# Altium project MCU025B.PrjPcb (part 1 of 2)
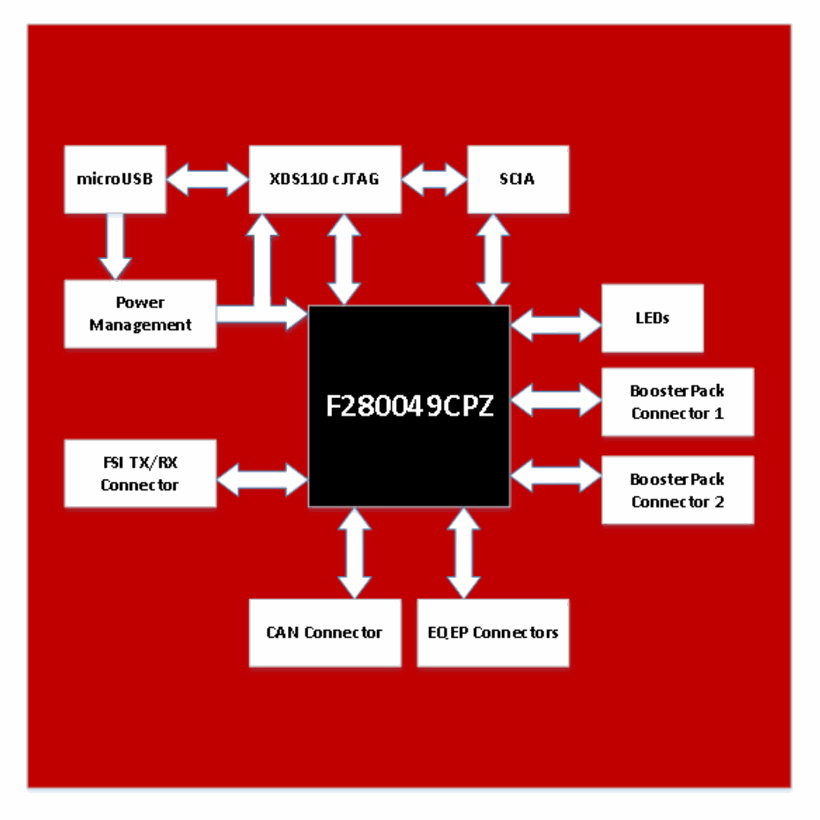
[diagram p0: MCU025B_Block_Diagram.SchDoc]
CopyrightYear: 2019; PCB_Layout: a0232540; PCB_Rev: B; PRJ_Customer: Public Release; PRJ_Engineer: a0232540; PRJ_Number: MCU025; PRJ_Title: LAUNCHXL-F280049C; SCH_Rev: B; TechSupport: http://www.ti.com/support; TID: N/A
8 sheets, 239 parts. Net scope: global (net labels, ports and power ports of the same name join across sheets).
Board file: MCU025B.PcbDoc
Sheets:
  MCU025B_Block_Diagram.SchDoc
  MCU025B_Connectors.SchDoc
  MCU025B_AltRouting_Misc.SchDoc
  MCU025B_F280049C_Device.SchDoc
  MCU025B_XDS110_Target_Interface.SchDoc
  MCU025B_XDS110_USB_Power.SchDoc
  MCU025B_XDS110_MCU.SchDoc
  MCU025B_Hardware.SchDoc

## Sheet MCU025B_Block_Diagram.SchDoc
size 431 x 279 mm; Date: Not shown in title block; ApprovedBy: Not shown in title block; CheckedBy: Not shown in title block; Author: Not shown in title block; CompanyName: Not shown in title block; Engineer: Not shown in title block; Organization: Not shown in title block; Address1: Not shown in title block; Address2: Not shown in title block; Address3: Not shown in title block; Address4: Not shown in title block; DocumentNumber: 1; Revision: Use project parameter SCH_Rev; SheetNumber: 1; SheetTotal: 8; PageSetup: Record=PageOptions¦CenterHorizontal=True¦CenterVertical=True¦PrintScale=1.00¦XCorrection=1.00¦YCorrection=1.00¦PrintKind=0¦BorderSize=5000000¦LeftOffset=0¦BottomOffset=0¦Orientation=2¦PaperLength=1000¦PaperWidth=1000¦Scale=100¦PaperSource=15¦PrintQuality=600¦MediaType=1¦DitherType=10¦PaperKind=Letter¦PrintScaleMode=1

## Sheet MCU025B_Connectors.SchDoc
size 431 x 279 mm; Date: Not shown in title block; ApprovedBy: Not shown in title block; CheckedBy: Not shown in title block; Author: Not shown in title block; CompanyName: Not shown in title block; Engineer: Not shown in title block; Organization: Not shown in title block; Address1: Not shown in title block; Address2: Not shown in title block; Address3: Not shown in title block; Address4: Not shown in title block; DocumentNumber: 2; Revision: Use project parameter SCH_Rev; SheetNumber: 2; SheetTotal: 8; PageSetup: Record=PageOptions¦CenterHorizontal=True¦CenterVertical=True¦PrintScale=1.00¦XCorrection=1.00¦YCorrection=1.00¦PrintKind=0¦BorderSize=5000000¦LeftOffset=0¦BottomOffset=0¦Orientation=2¦PaperLength=1000¦PaperWidth=1000¦Scale=100¦PaperSource=15¦PrintQuality=600¦MediaType=1¦DitherType=10¦PaperKind=Letter¦PrintScaleMode=1
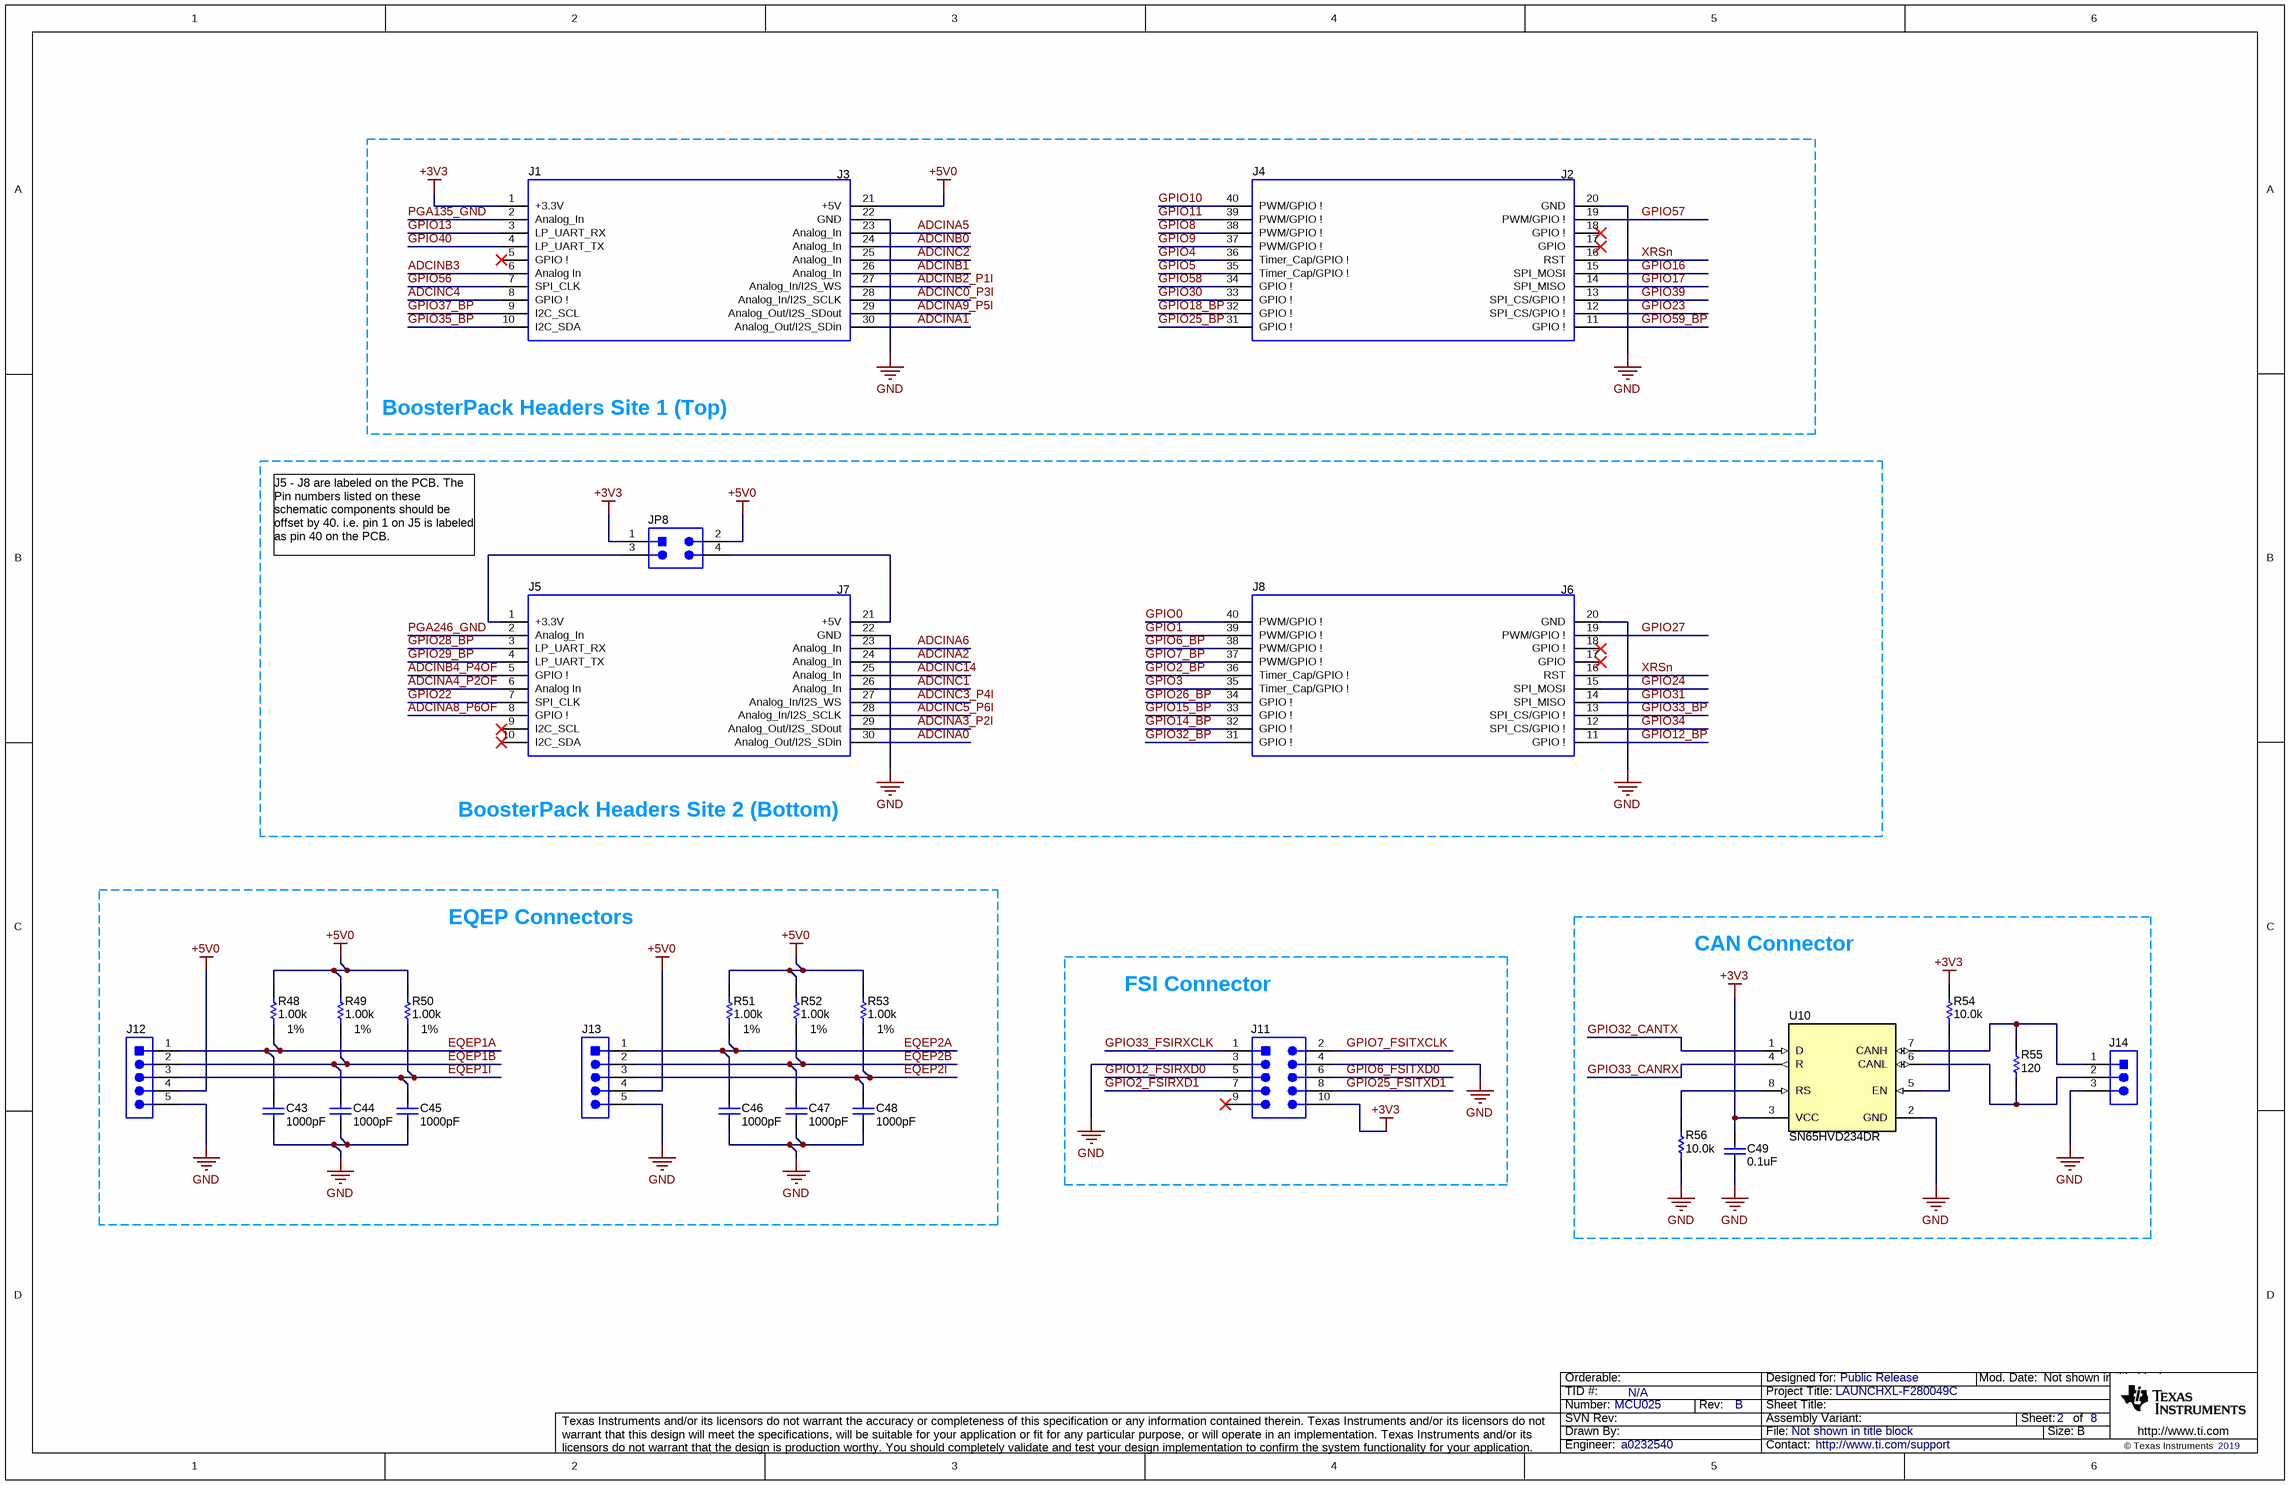
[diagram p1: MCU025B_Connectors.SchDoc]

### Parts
C43  ValueDisplayed: 1000pF  [0402]  (hidden comment: GRM155R71H102KA01D)
C44  ValueDisplayed: 1000pF  [0402]  (hidden comment: GRM155R71H102KA01D)
C45  ValueDisplayed: 1000pF  [0402]  (hidden comment: GRM155R71H102KA01D)
C46  ValueDisplayed: 1000pF  [0402]  (hidden comment: GRM155R71H102KA01D)
C47  ValueDisplayed: 1000pF  [0402]  (hidden comment: GRM155R71H102KA01D)
C48  ValueDisplayed: 1000pF  [0402]  (hidden comment: GRM155R71H102KA01D)
C49  ValueDisplayed: 0.1uF  [0402]  (hidden comment: GRM155R71A104KA01D)
J1  SSQ-110-03-T-D  [BoosterPack_40pin_J1J3]  (value not drawn)
J4  SSQ-110-03-T-D  [BoosterPack_40pin_J2J4]  (value not drawn)
J5  SSQ-110-03-T-D  [BoosterPack_40pin_J1J3]  (value not drawn)
J8  SSQ-110-03-T-D  [BoosterPack_40pin_J2J4]  (value not drawn)
J11  TSW-105-07-G-D  [TSW-105-07-G-D]  (value not drawn)
J12  TSW-105-07-G-S  [TSW-105-07-X-S]  (value not drawn)
J13  TSW-105-07-G-S  [TSW-105-07-X-S]  (value not drawn)
J14  61300311121  [WURTH_61300311121]  (value not drawn)
JP8  TSW-102-07-G-D  [TSW-102-07-G-D]  (value not drawn)
R48  ValueDisplayed: 1.00k  Value1: 1%  [0402]  (hidden comment: CRCW04021K00FKED)
R49  ValueDisplayed: 1.00k  Value1: 1%  [0402]  (hidden comment: CRCW04021K00FKED)
R50  ValueDisplayed: 1.00k  Value1: 1%  [0402]  (hidden comment: CRCW04021K00FKED)
R51  ValueDisplayed: 1.00k  Value1: 1%  [0402]  (hidden comment: CRCW04021K00FKED)
R52  ValueDisplayed: 1.00k  Value1: 1%  [0402]  (hidden comment: CRCW04021K00FKED)
R53  ValueDisplayed: 1.00k  Value1: 1%  [0402]  (hidden comment: CRCW04021K00FKED)
R54  ValueDisplayed: 10.0k  [0402]  (hidden comment: CRCW040210K0FKED)
R55  ValueDisplayed: 120  [0603]  (hidden comment: RC0603FR-07120RL)
R56  ValueDisplayed: 10.0k  [0402]  (hidden comment: CRCW040210K0FKED)
U10  SN65HVD234DR  [D0008A_L]

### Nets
+3V3: C49.2 J1.1(+3.3V) J11.10 JP8.1 R54.2 U10.3(VCC)
+5V0: J1.21(+5V) J12.4 J13.4 JP8.2 R48.2 R49.2 R50.2 R51.2 R52.2 R53.2
GND: C43.2 C44.2 C45.2 C46.2 C47.2 C48.2 C49.1 J1.22(GND) J4.20(GND) J5.22(GND) J8.20(GND) J11.3 J11.4 J12.5 J13.5 J14.3 R56.1 U10.2(GND)
ADCINA0: J5.30(Analog_Out/I2S_SDin)
ADCINA1: J1.30(Analog_Out/I2S_SDin)
ADCINA2: J5.24(Analog_In)
ADCINA3_P2I: J5.29(Analog_Out/I2S_SDout)
ADCINA4_P2OF: J5.6(Analog_In)
ADCINA5: J1.23(Analog_In)
ADCINA6: J5.23(Analog_In)
ADCINA8_P6OF: J5.8(GPIO_!)
ADCINA9_P5I: J1.29(Analog_Out/I2S_SDout)
ADCINB0: J1.24(Analog_In)
ADCINB1: J1.26(Analog_In)
ADCINB2_P1I: J1.27(Analog_In/I2S_WS)
ADCINB3: J1.6(Analog_In)
ADCINB4_P4OF: J5.5(GPIO_!)
ADCINC0_P3I: J1.28(Analog_In/I2S_SCLK)
ADCINC1: J5.26(Analog_In)
ADCINC2: J1.25(Analog_In)
ADCINC3_P4I: J5.27(Analog_In/I2S_WS)
ADCINC4: J1.8(GPIO_!)
ADCINC5_P6I: J5.28(Analog_In/I2S_SCLK)
ADCINC14: J5.25(Analog_In)
EQEP1A: C43.1 J12.1 R48.1
EQEP1B: C44.1 J12.2 R49.1
EQEP1I: C45.1 J12.3 R50.1
EQEP2A: C46.1 J13.1 R51.1
EQEP2B: C47.1 J13.2 R52.1
EQEP2I: C48.1 J13.3 R53.1
GPIO0: J8.40(PWM/GPIO_!)
GPIO1: J8.39(PWM/GPIO_!)
GPIO2_BP: J8.36(Timer_Cap/GPIO_!)
GPIO2_FSIRXD1: J11.7
GPIO3: J8.35(Timer_Cap/GPIO_!)
GPIO4: J4.36(Timer_Cap/GPIO_!)
GPIO5: J4.35(Timer_Cap/GPIO_!)
GPIO6_BP: J8.38(PWM/GPIO_!)
GPIO6_FSITXD0: J11.6
GPIO7_BP: J8.37(PWM/GPIO_!)
GPIO7_FSITXCLK: J11.2
GPIO8: J4.38(PWM/GPIO_!)
GPIO9: J4.37(PWM/GPIO_!)
GPIO10: J4.40(PWM/GPIO_!)
GPIO11: J4.39(PWM/GPIO_!)
GPIO12_BP: J8.11(GPIO_!)
GPIO12_FSIRXD0: J11.5
GPIO13: J1.3(LP_UART_RX)
GPIO14_BP: J8.32(GPIO_!)
GPIO15_BP: J8.33(GPIO_!)
GPIO16: J4.15(SPI_MOSI)
GPIO17: J4.14(SPI_MISO)
GPIO18_BP: J4.32(GPIO_!)
GPIO22: J5.7(SPI_CLK)
GPIO23: J4.12(SPI_CS/GPIO_!)
GPIO24: J8.15(SPI_MOSI)
GPIO25_BP: J4.31(GPIO_!)
GPIO25_FSITXD1: J11.8
GPIO26_BP: J8.34(GPIO_!)
GPIO27: J8.19(PWM/GPIO_!)
GPIO28_BP: J5.3(LP_UART_RX)
GPIO29_BP: J5.4(LP_UART_TX)
GPIO30: J4.33(GPIO_!)
GPIO31: J8.14(SPI_MISO)
GPIO32_BP: J8.31(GPIO_!)
GPIO32_CANTX: U10.1(D)
GPIO33_BP: J8.13(SPI_CS/GPIO_!)
GPIO33_CANRX: U10.4(R)
GPIO33_FSIRXCLK: J11.1
GPIO34: J8.12(SPI_CS/GPIO_!)
GPIO35_BP: J1.10(I2C_SDA)
GPIO37_BP: J1.9(I2C_SCL)
GPIO39: J4.13(SPI_CS/GPIO_!)
GPIO40: J1.4(LP_UART_TX)
GPIO56: J1.7(SPI_CLK)
GPIO57: J4.19(PWM/GPIO_!)
GPIO58: J4.34(GPIO_!)
GPIO59_BP: J4.11(GPIO_!)
PGA135_GND: J1.2(Analog_In)
PGA246_GND: J5.2(Analog_In)
XRSn: J4.16(RST) J8.16(RST)
NetJ5_1: J5.1(+3.3V) JP8.3
NetJ5_21: J5.21(+5V) JP8.4
NetJ14_1: J14.1 R55.2 U10.7(CANH)
NetJ14_2: J14.2 R55.1 U10.6(CANL)
NetR54_1: R54.1 U10.5(EN)
NetR56_2: R56.2 U10.8(RS)

Not connected (* = marked no-connect by the designer): J1 5(GPIO_!)*; J4 17(GPIO)* 18(GPIO_!)*; J5 9(I2C_SCL)* 10(I2C_SDA)*; J8 17(GPIO)* 18(GPIO_!)*; J11 9*

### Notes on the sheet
- (near J1) J3
- (near J4) J2
- BoosterPack Headers Site 1 (Top)
- J5 - J8 are labeled on the PCB. The Pin numbers listed on these schematic components should be offset by 40. i.e. pin 1 on J5 is labeled as pin 40 on the PCB.
- (near J5) J7
- (near J8) J6
- BoosterPack Headers Site 2 (Bottom)
- EQEP Connectors
- CAN Connector
- FSI Connector

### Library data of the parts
C43-C48 = CMP-0006673-2: CAP, CERM, 1000 pF, 50 V, +/- 10%, X7R, 0402; Manufacturer: MuRata; Polarized: N; Value: 1000pF; U/M: EA; Cap_F: 1nF; Value1: Unknown; VDC_V: 50V; TaMin_C: -55°C; TaMax_C: 125°C; SizeArea_mm2: 0.5; SizeAreaWB_mm2: 3; SizeX_mm: 1; SizeZ_mm: 0.6; AEC Category: Q200
C49 = CMP-0006629-2: CAP, CERM, 0.1 uF, 10 V, +/- 10%, X7R, 0402; Manufacturer: MuRata; Polarized: N; Value: 0.1uF; U/M: EA; Cap_F: 100nF; Value1: Unknown; VDC_V: 10V; TaMin_C: -55°C; TaMax_C: 125°C; SizeArea_mm2: 0.5; SizeAreaWB_mm2: 3; SizeX_mm: 1; SizeZ_mm: 0.6; AEC Category: Q200
J1 J5 = CMP-0003837-2: Receptacle, 2.54mm, 10x2, Tin, TH; Manufacturer: Samtec; Alternate Manufacturer: Major League Electronics; Alternate PartNumber: CRD-081413-A-G; Note: Booster Pack 40 pin J1 and J3; Green_Lifecycle: Active; Green_REACh: Incomplete
J4 J8 = CMP-0078266-2: Receptacle, 2.54mm, 10x2, Tin, TH; Manufacturer: Samtec; Alternate Manufacturer: Major League Electronics; Alternate PartNumber: CRD-081413-A-G; Note: Booster Pack 40 pin J2 and J4; Green_Lifecycle: Active; Green_REACh: Incomplete
J11 = CMP-0075410-2: Header, 100mil, 5x2, Gold, TH; Manufacturer: Samtec; Pitch_mm: 2.54; Cert_VDE: N; Gender: Male; Cert_CSA: Y; Voltage_V: 550V; Green_REACh: Passed; Current_A: 6.3A; Green_Lifecycle: Active; Row_Count: 2
J12 J13 = CMP-0075411-1: Header, 100mil, 5x1, Gold, TH; Manufacturer: Samtec; Pitch_mm: 2.54; Cert_VDE: N; Gender: Male; Cert_CSA: Y; Voltage_V: 550V; Green_REACh: Passed; Current_A: 6.3A; CT: False; Green_Lifecycle: Active; Row_Count: 1; CNHeader: True
J14 = CMP-0054796-1: Header, 2.54 mm, 3x1, Gold, TH; Manufacturer: Wurth Elektronik; Green_Lifecycle: Active; Green_REACh: Passed; CNHeader: TRUE; CT: FALSE
JP8 = CMP-0075404-1: Header, 100mil, 2x2, Gold, TH; Manufacturer: Samtec; CNHeader: True; Shrouded: N; Gender: Male; Row_Count: 2; RowSpacing_mm: 2.54; CT: False; Cert_CSA: Y; Current_A: 6.3A; Green_Lifecycle: Active; Green_REACh: Passed; Voltage_V: 550V
R48-R53 = CMP-0026071-3: RES, 1.00 k, 1%, 0.063 W, AEC-Q200 Grade 0, 0402; Manufacturer: Vishay-Dale; Value: 1.00k; Res_ohm: 1k; Value_Code: 1k00; Power_W: 63mW; Value2: 0.063W; VDC_V: 50V; TempCo: 100 ppm/C; SizeArea_mm2: 0.5; SizeX_mm: 1; SizeZ_mm: 0.6; EIA_Code: E96; AEC Category: Q200; AEC Qualified: Y; AEC Grade: 0
R54 R56 = CMP-0025958-3: RES, 10.0 k, 1%, 0.063 W, AEC-Q200 Grade 0, 0402; Manufacturer: Vishay-Dale; Value: 10.0k; Res_ohm: 10k; Value_Code: 10k0; Power_W: 63mW; Value2: 0.063W; VDC_V: 50V; TempCo: 100 ppm/C; SizeArea_mm2: 0.5; SizeX_mm: 1; SizeZ_mm: 0.6; EIA_Code: E96; AEC Category: Q200; AEC Qualified: Y; AEC Grade: 0
R55 = CMP-0022769-3: RES, 120, 1%, 0.1 W, 0603; Manufacturer: Yageo America; Value: 120; Value_Code: 120R; Power_W: 100mW; Value2: 0.1W; VDC_V: 150V; TempCo: 200 ppm/C; SizeArea_mm2: 1.28; SizeX_mm: 1.6; SizeY_mm: 0.8; SizeZ_mm: 1; U/M: EA; AEC Category: Q200
U10 = CMP-0033355-1: 3.3V CAN Transceiver with Sleep Mode, 6 mA, -40 to 125 degC, 8-pin SOIC (D), Green (RoHS & no Sb/Br); Manufacturer: Texas Instruments; Drivers Per Package: 1; Bus Fault Voltage(V): +/-30; Transient Pulse Protection(V): -100 to 100; ICC(Max)(mA): 6; Supply Voltage(s)(V): 3.3; Rating: Catalog

## Sheet MCU025B_AltRouting_Misc.SchDoc
size 431 x 279 mm; Date: Not shown in title block; ApprovedBy: Not shown in title block; CheckedBy: Not shown in title block; Author: Not shown in title block; CompanyName: Not shown in title block; Engineer: Not shown in title block; Organization: Not shown in title block; Address1: Not shown in title block; Address2: Not shown in title block; Address3: Not shown in title block; Address4: Not shown in title block; DocumentNumber: 3; Revision: Use project parameter SCH_Rev; SheetNumber: 3; SheetTotal: 8; PageSetup: Record=PageOptions¦CenterHorizontal=True¦CenterVertical=True¦PrintScale=1.00¦XCorrection=1.00¦YCorrection=1.00¦PrintKind=0¦BorderSize=5000000¦LeftOffset=0¦BottomOffset=0¦Orientation=2¦PaperLength=1000¦PaperWidth=1000¦Scale=100¦PaperSource=15¦PrintQuality=600¦MediaType=1¦DitherType=10¦PaperKind=Letter¦PrintScaleMode=1
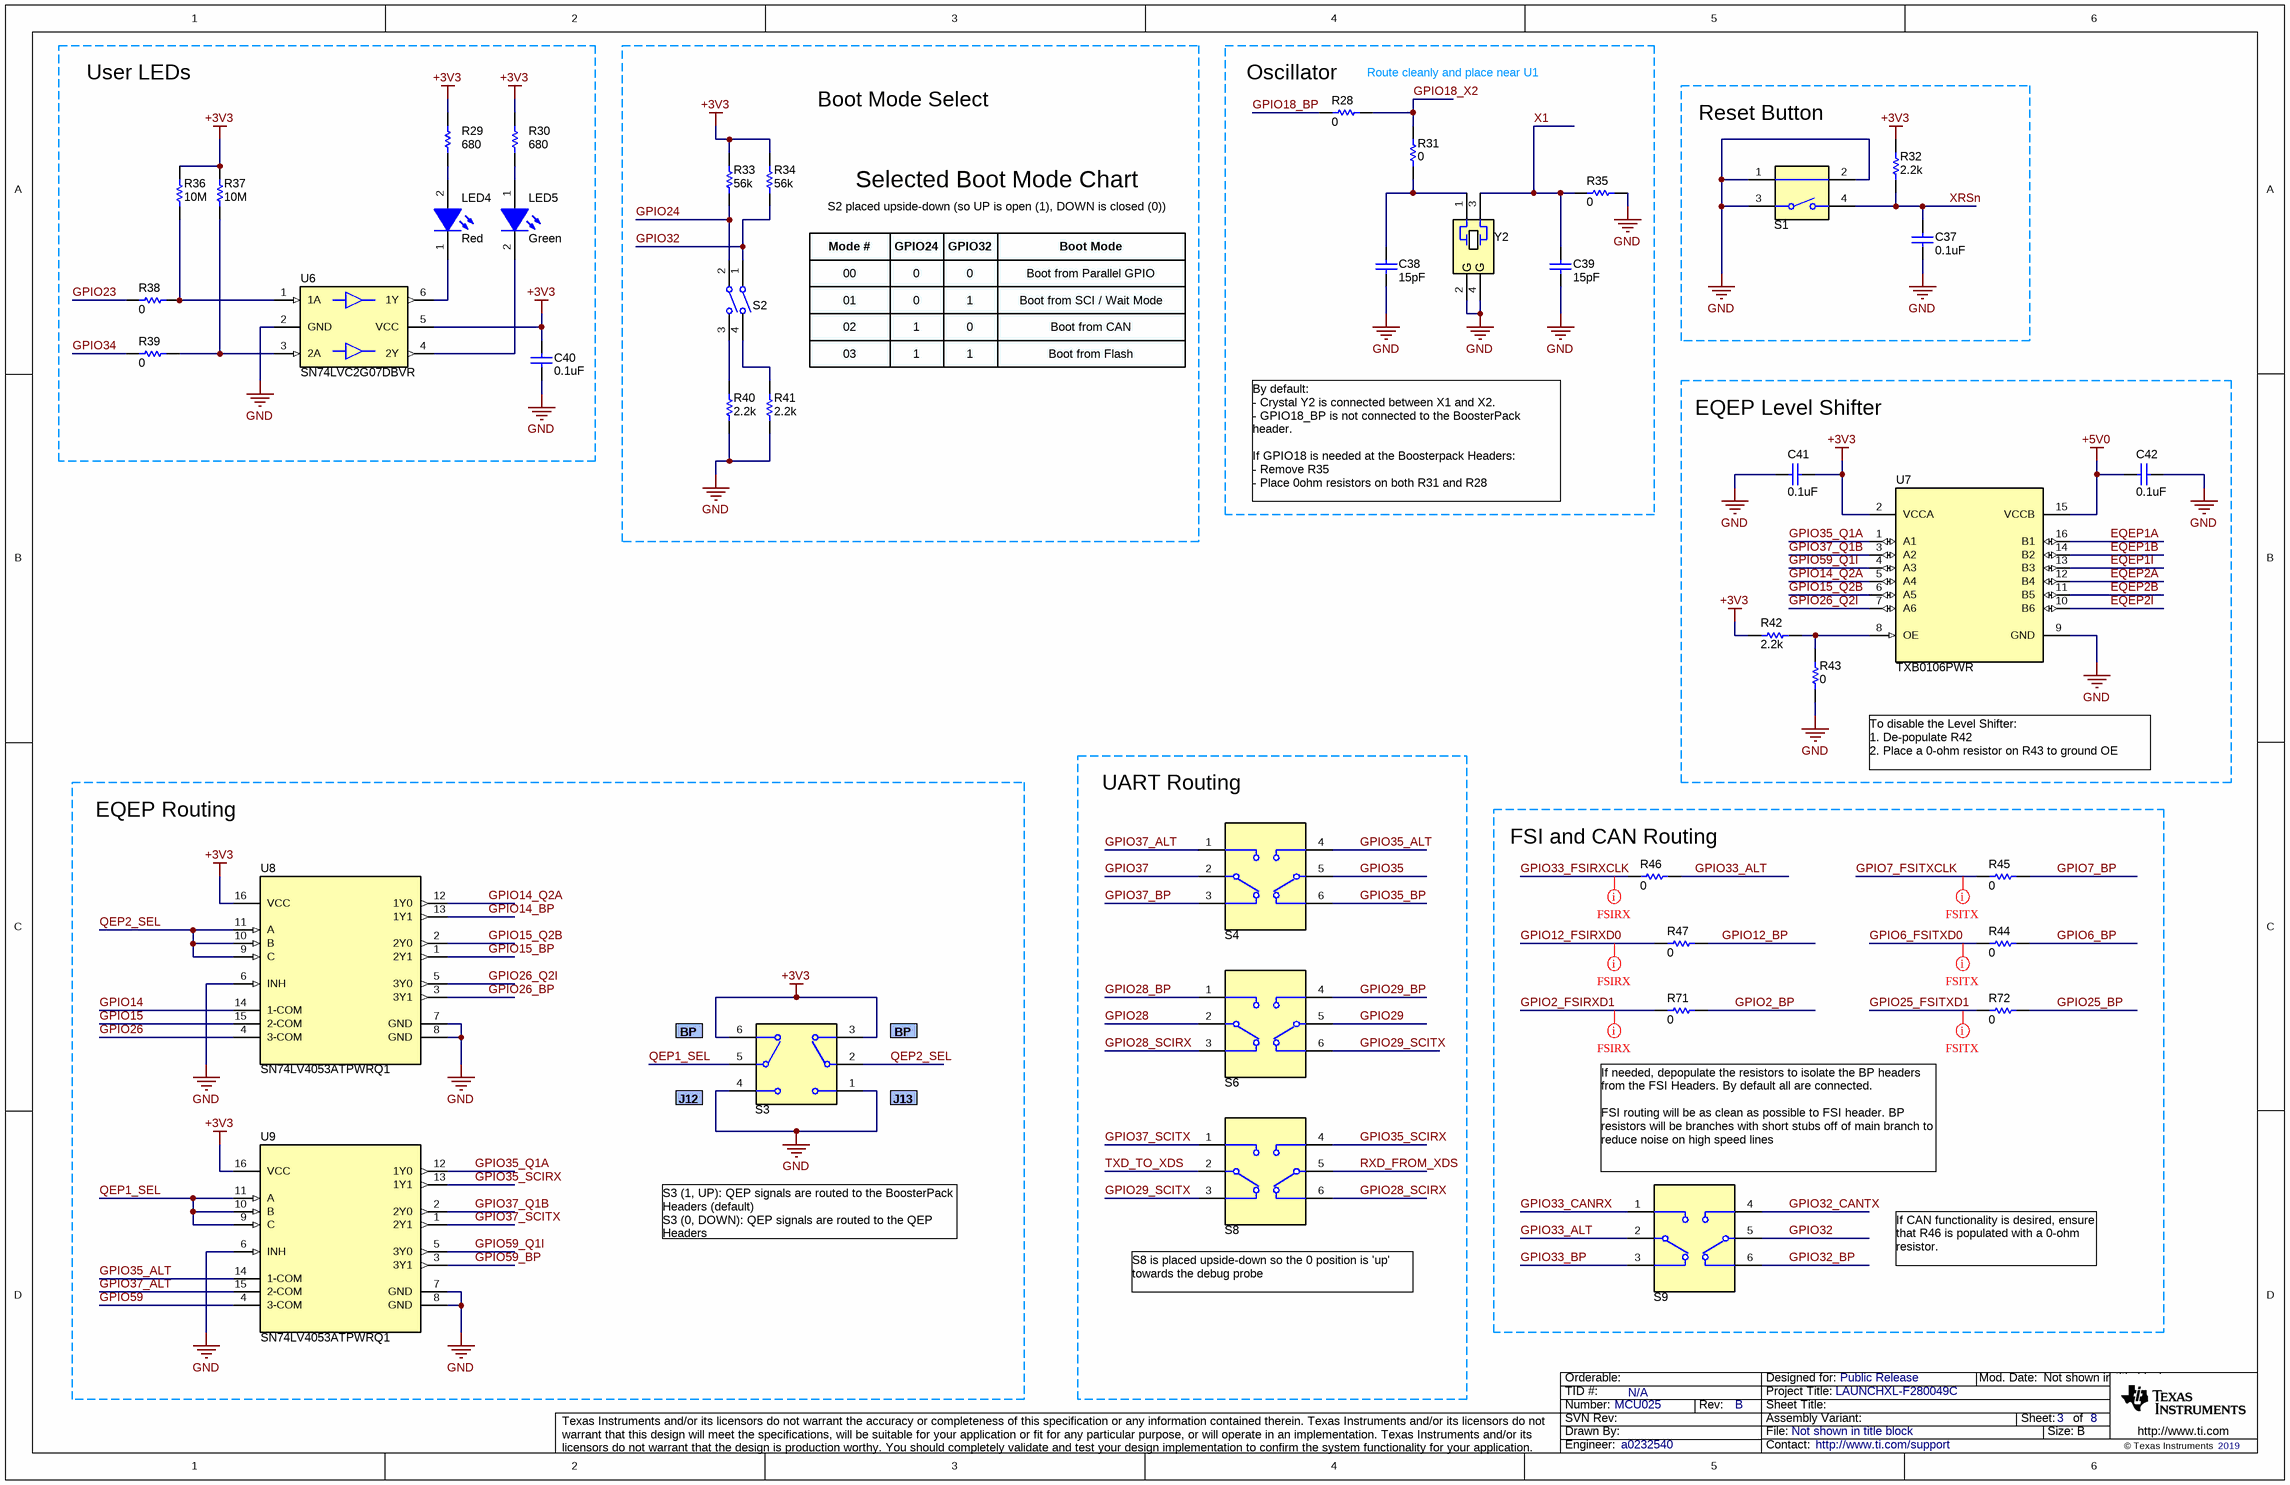
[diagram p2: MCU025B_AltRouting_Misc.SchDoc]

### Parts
C37  ValueDisplayed: 0.1uF  [0402]  (hidden comment: GRM155R71A104KA01D)
C38  ValueDisplayed: 15pF  [0402]  (hidden comment: GRM1555C1H150JA01D)
C39  ValueDisplayed: 15pF  [0402]  (hidden comment: GRM1555C1H150JA01D)
C40  ValueDisplayed: 0.1uF  [0402]  (hidden comment: GRM155R71A104KA01D)
C41  ValueDisplayed: 0.1uF  [0402]  (hidden comment: GRM155R71A104KA01D)
C42  ValueDisplayed: 0.1uF  [0402]  (hidden comment: GRM155R71A104KA01D)
LED4  value Red  [WL-SMCW_RED_0805]  (hidden comment: 150080SS75000)
LED5  value Green  [LED_LTST-C171]  (hidden comment: LTST-C171GKT)
R28  ValueDisplayed: 0  [0603]  (hidden comment: CRCW06030000Z0EA)
R29  ValueDisplayed: 680  [0402]  (hidden comment: CRCW0402680RJNED)
R30  ValueDisplayed: 680  [0402]  (hidden comment: CRCW0402680RJNED)
R31  ValueDisplayed: 0  [0603]  (hidden comment: CRCW06030000Z0EA)
R32  ValueDisplayed: 2.2k  [0402]  (hidden comment: CRCW04022K20JNED)
R33  ValueDisplayed: 56k  [0402]  (hidden comment: CRCW040256K0JNED)
R34  ValueDisplayed: 56k  [0402]  (hidden comment: CRCW040256K0JNED)
R35  ValueDisplayed: 0  [0603]  (hidden comment: CRCW06030000Z0EA)
R36  ValueDisplayed: 10M  [0402]  (hidden comment: CRCW040210M0JNED)
R37  ValueDisplayed: 10M  [0402]  (hidden comment: CRCW040210M0JNED)
R38  ValueDisplayed: 0  [0603]  (hidden comment: CRCW06030000Z0EA)
R39  ValueDisplayed: 0  [0603]  (hidden comment: CRCW06030000Z0EA)
R40  ValueDisplayed: 2.2k  [0402]  (hidden comment: CRCW04022K20JNED)
R41  ValueDisplayed: 2.2k  [0402]  (hidden comment: CRCW04022K20JNED)
R42  ValueDisplayed: 2.2k  [0603]  (hidden comment: CRCW06032K20JNEA)
R43  ValueDisplayed: 0  [0603]  (hidden comment: CRCW06030000Z0EA)
R44  ValueDisplayed: 0  [0603]  (hidden comment: CRCW06030000Z0EA)
R45  ValueDisplayed: 0  [0603]  (hidden comment: CRCW06030000Z0EA)
R46  ValueDisplayed: 0  [0603]  (hidden comment: CRCW06030000Z0EA)
R47  ValueDisplayed: 0  [0603]  (hidden comment: CRCW06030000Z0EA)
R71  ValueDisplayed: 0  [0603]  (hidden comment: CRCW06030000Z0EA)
R72  ValueDisplayed: 0  [0603]  (hidden comment: CRCW06030000Z0EA)
S1  1188E-1K2-V-TR  [SW_1188E]  (value not drawn)
S2  218-2LPST  [SW_218-2LP]  (value not drawn)
S3  CAS-D20TA  [SW_CAS-D20TA]  (value not drawn)
S4  CAS-220TA  [SW_CAS-220TA]  (value not drawn)
S6  CAS-220TA  [SW_CAS-220TA]  (value not drawn)
S8  CAS-220TA  [SW_CAS-220TA]  (value not drawn)
S9  CAS-220TA  [SW_CAS-220TA]  (value not drawn)
U6  SN74LVC2G07DBVR  [DBV0006A_N]
U7  TXB0106PWR  [PW0016A_N]
U8  SN74LV4053ATPWRQ1  [PW0016A_L]
U9  SN74LV4053ATPWRQ1  [PW0016A_L]
Y2  ECS-200-18-30B-AGN-TR  [ECS_ECX-53B]  (value not drawn)

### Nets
+3V3: C40.2 C41.1 R29.2 R30.2 R32.2 R33.2 R34.2 R36.2 R37.2 R42.1 S3.3 S3.6 U6.5(VCC) U7.2(VCCA) U8.16(VCC) U9.16(VCC)
+5V0: C42.2 U7.15(VCCB)
GND: C37.1 C38.2 C39.2 C40.1 C41.2 C42.1 R35.2 R40.1 R41.1 R43.1 S1.1 S1.2 S1.3 S3.1 S3.4 U6.2(GND) U7.9(GND) U8.6(INH) U8.7(GND) U8.8(GND) U9.6(INH) U9.7(GND) U9.8(GND) Y2.2(GND) Y2.4(GND)
EQEP1A: U7.16(B1)
EQEP1B: U7.14(B2)
EQEP1I: U7.13(B3)
EQEP2A: U7.12(B4)
EQEP2B: U7.11(B5)
EQEP2I: U7.10(B6)
GPIO2_BP: R71.2
GPIO2_FSIRXD1: R71.1
GPIO6_BP: R44.2
GPIO6_FSITXD0: R44.1
GPIO7_BP: R45.2
GPIO7_FSITXCLK: R45.1
GPIO12_BP: R47.2
GPIO12_FSIRXD0: R47.1
GPIO14: U8.14(1-COM)
GPIO14_BP: U8.13(1Y1)
GPIO14_Q2A: U7.5(A4) U8.12(1Y0)
GPIO15: U8.15(2-COM)
GPIO15_BP: U8.1(2Y1)
GPIO15_Q2B: U7.6(A5) U8.2(2Y0)
GPIO18_BP: R28.1
GPIO18_X2: R28.2 R31.2
GPIO23: R38.1
GPIO24: R33.1 S2.2
GPIO25_BP: R72.2
GPIO25_FSITXD1: R72.1
GPIO26: U8.4(3-COM)
GPIO26_BP: U8.3(3Y1)
GPIO26_Q2I: U7.7(A6) U8.5(3Y0)
GPIO28: S6.2
GPIO28_BP: S6.1
GPIO28_SCIRX: S6.3 S8.6
GPIO29: S6.5
GPIO29_BP: S6.4
GPIO29_SCITX: S6.6 S8.3
GPIO32: R34.1 S2.1 S9.5
GPIO32_BP: S9.6
GPIO32_CANTX: S9.4
GPIO33_ALT: R46.2 S9.2
GPIO33_BP: S9.3
GPIO33_CANRX: S9.1
GPIO33_FSIRXCLK: R46.1
GPIO34: R39.1
GPIO35: S4.5
GPIO35_ALT: S4.4 U9.14(1-COM)
GPIO35_BP: S4.6
GPIO35_Q1A: U7.1(A1) U9.12(1Y0)
GPIO35_SCIRX: S8.4 U9.13(1Y1)
GPIO37: S4.2
GPIO37_ALT: S4.1 U9.15(2-COM)
GPIO37_BP: S4.3
GPIO37_Q1B: U7.3(A2) U9.2(2Y0)
GPIO37_SCITX: S8.1 U9.1(2Y1)
GPIO59: U9.4(3-COM)
GPIO59_BP: U9.3(3Y1)
GPIO59_Q1I: U7.4(A3) U9.5(3Y0)
QEP1_SEL: S3.5(C) U9.9(C) U9.10(B) U9.11(A)
QEP2_SEL: S3.2(C) U8.9(C) U8.10(B) U8.11(A)
RXD_FROM_XDS: S8.5
TXD_TO_XDS: S8.2
X1: C39.1 R35.1 Y2.3
XRSn: C37.2 R32.1 S1.4
NetC38_1: C38.1 R31.1 Y2.1
NetLED4_1: LED4.1(K) U6.6(1Y)
NetLED4_2: LED4.2(A) R29.1
NetLED5_1: LED5.1(A) R30.1
NetLED5_2: LED5.2(K) U6.4(2Y)
NetR36_1: R36.1 R38.2 U6.1(1A)
NetR37_1: R37.1 R39.2 U6.3(2A)
NetR40_2: R40.2 S2.3
NetR41_2: R41.2 S2.4
NetR42_2: R42.2 R43.2 U7.8(OE)

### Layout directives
net class FSIRX: GPIO2_FSIRXD1, GPIO12_FSIRXD0, GPIO33_FSIRXCLK
net class FSITX: GPIO6_FSITXD0, GPIO7_FSITXCLK, GPIO25_FSITXD1

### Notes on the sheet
- User LEDs
- Boot Mode Select
- (near R28) Oscillator
- (near R28) Route cleanly and place near U1
- Reset Button
- Selected Boot Mode Chart
- (near R34) S2 placed upside-down (so UP is open (1), DOWN is closed (0))
- Mode #
- 00
- 01
- GPIO24
- 0
- GPIO32
- 1
- Boot Mode
- Boot from Parallel GPIO
- Boot from SCI / Wait Mode
- 02
- 03
- Boot from CAN
- Boot from Flash
- EQEP Level Shifter
- By default:
  - Crystal Y2 is connected between X1 and X2.
  - GPIO18_BP is not connected to the BoosterPack header.
  If GPIO18 is needed at the Boosterpack Headers:
  - Remove R35
  - Place 0ohm resistors on both R31 and R28
- To disable the Level Shifter:
  1. De-populate R42
  2. Place a 0-ohm resistor on R43 to ground OE
- EQEP Routing
- UART Routing
- (near R46) FSI and CAN Routing
- BP
- J12
- J13
- If needed, depopulate the resistors to isolate the BP headers from the FSI Headers. By default all are connected.
  FSI routing will be as clean as possible to FSI header. BP resistors will be branches with short stubs off of main branch to reduce noise on high speed lines
- S3 (1, UP): QEP signals are routed to the BoosterPack Headers (default)
  S3 (0, DOWN): QEP signals are routed to the QEP Headers
- S8 is placed upside-down so the 0 position is 'up' towards the debug probe
- If CAN functionality is desired, ensure that R46 is populated with a 0-ohm resistor.

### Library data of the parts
C37 C40-C42 = CMP-0006629-2: as C49 on sheet MCU025B_Connectors
C38 C39 = CMP-0006420-2: CAP, CERM, 15 pF, 50 V, +/- 5%, C0G/NP0, 0402; Manufacturer: MuRata; Polarized: N; Value: 15pF; U/M: EA; Value1: Unknown; VDC_V: 50V; TaMin_C: -55°C; TaMax_C: 125°C; SizeArea_mm2: 0.5; SizeAreaWB_mm2: 3; SizeX_mm: 1; SizeZ_mm: 0.6; AEC Category: Q200
LED4 = CMP-0002951-2: LED, Red, SMD; Manufacturer: Wurth Elektronik; Type: AlInGaP; Vf_V: 1.9V; Io_A: 30mA; Vr_V: 5V; Ir_A: 25µA; Tjmax_C: 85°C; Power_TotalModule: 72mW; Value1: 0.072W; Angle: 140; U/M: EA
LED5 = CMP-0002830-2: LED, Green, SMD; Manufacturer: Lite-On; Type: AlInGaP; Vf_V: 2.1V; Io_A: 20A; Value1: W; SizeAreaWB_mm2: 6.75; SizeArea_mm2: 2.5; SizeX_mm: 2; SizeY_mm: 1.25; SizeZ_mm: 1.2; U/M: EA
R28 R31 R35 R38 R39 R43-R47 R71 R72 = CMP-0025697-4: RES, 0, 5%, 0.1 W, AEC-Q200 Grade 0, 0603; Manufacturer: Vishay-Dale; Value: 0; Value_Code: 0000; Power_W: 100mW; Value2: 0.1W; VDC_V: 75V; TempCo: 200 ppm/C; SizeArea_mm2: 1.28; SizeX_mm: 1.6; SizeY_mm: 0.8; SizeZ_mm: 1; EIA_Code: E24; AEC Category: Q200; AEC Qualified: Y
R29 R30 = CMP-0026962-3: RES, 680, 5%, 0.063 W, AEC-Q200 Grade 0, 0402; Manufacturer: Vishay-Dale; Power_W: 63mW; TempCo: 200 ppm/C; Value_Code: 680R; Value: 680; EIA_Code: E24; SizeX_mm: 1; SizeY_mm: 0.5; SizeZ_mm: 0.6; Value2: 0.063W; CompType: Resistor; AEC Qualified: Y; VDC_V: 50V; AEC Category: Q200; AEC Grade: 0
R32 R40 R41 = CMP-0026890-5: RES, 2.2 k, 5%, 0.063 W, AEC-Q200 Grade 0, 0402; Manufacturer: Vishay-Dale; Value: 2.2k; Value_Code: 2k20; Power_W: 63mW; Value2: 0.063W; VDC_V: 50V; TempCo: 200 ppm/C; SizeArea_mm2: 0.5; SizeX_mm: 1; SizeZ_mm: 0.6; EIA_Code: E24; AEC Category: Q200; AEC Qualified: Y; AEC Grade: 0
R33 R34 = CMP-0026949-3: RES, 56 k, 5%, 0.063 W, AEC-Q200 Grade 0, 0402; Manufacturer: Vishay-Dale; Value: 56k; Value_Code: 56k0; Power_W: 63mW; Value2: 0.063W; VDC_V: 50V; TempCo: 200 ppm/C; SizeArea_mm2: 0.5; SizeX_mm: 1; SizeZ_mm: 0.6; EIA_Code: E24; AEC Category: Q200; AEC Qualified: Y; AEC Grade: 0
R36 R37 = CMP-0026826-2: RES, 10 M, 5%, 0.063 W, AEC-Q200 Grade 0, 0402; Manufacturer: Vishay-Dale; Value: 10Meg; Value_Code: 10M0; Power_W: 63mW; Value2: 0.063W; VDC_V: 50V; TempCo: 200 ppm/C; SizeArea_mm2: 0.5; SizeX_mm: 1; SizeZ_mm: 0.6; EIA_Code: E24; AEC Category: Q200; AEC Qualified: Y; AEC Grade: 0
R42 = CMP-0025769-4: RES, 2.2 k, 5%, 0.1 W, AEC-Q200 Grade 0, 0603; Manufacturer: Vishay-Dale; Value: 2.2k; Value_Code: 2k20; Power_W: 100mW; Value2: 0.1W; VDC_V: 75V; TempCo: 200 ppm/C; SizeArea_mm2: 1.28; SizeX_mm: 1.6; SizeY_mm: 0.8; SizeZ_mm: 1; EIA_Code: E24; AEC Category: Q200; AEC Qualified: Y; AEC Grade: 0
S1 = CMP-0002328-1: Switch, SPST, 0.05 A, 12 VDC, SMD; Manufacturer: Diptronics; SizeAreaWB_mm2: 53.9; SizeArea_mm2: 27.3; SizeX_mm: 7.8; SizeY_mm: 3.5; VDC_V: 12V; PositionCount: 1; CurrentRating_mA: 50A
S2 = CMP-0002230-1: Switch, SPST, 2 Pos, 25mA, 24VDC, SMD; Manufacturer: CTS Electrocomponents; VDC_V: 24V; SwitchFunction: Off-On; PositionCount: 2; CurrentRating_mA: 25A
S3 = CMP-0002233-1: Switch, Dual SPDT,  2 Pos, 0.1A, 6VDC, SMD; Manufacturer: Copal Electronics; VDC_V: 6V; SwitchFunction: On-On; PositionCount: 2; CurrentRating_mA: 100A
S4 S6 S8 S9 = CMP-0002123-2: SLIDE SWITCH DPDT  .1A, SMT; Manufacturer: Copal Electronics; VDC_V: 6V; SwitchFunction: On-On; PositionCount: 2; CurrentRating_mA: 100A
U6 = CMP-0051789-2: Dual Buffer/Driver with Open-Drain Output, DBV0006A, LARGE T&R; Manufacturer: Texas Instruments; VCC(Min)(V): 1.65; VCC(Max)(V): 5.5; Output Type: CMOS; ICC @ Nom Voltage(Max)(mA): 0.01; Input Type: CMOS/TTL; Bits(#): 2; F @ Nom Voltage(Max)(Mhz): 150; Rating: Catalog; Technology Family: LVC; Voltage(Nom)(V): 1.8,2.5,3.3,5; Schmitt Trigger: No; Output Drive (IOL/IOH)(Max)(mA): 32/-32; tpd @ Nom Voltage(Max)(ns): 8.6,4.4,3.7,2.9; Logic: True; Sub-Family: Inverting Buffer/Driver; AEC Category: Q200; AEC Qualified: N; CompType: IC; Green_Lifecycle: Active; Green_REACh: Passed; SizeArea_mm2: 8.12; SizeAreaWB_mm2: 14.82; SizeX_mm: 2.8; SizeY_mm: 2.9; SizeZ_mm: 1.45
U7 = CMP-0067443-1: 6-Bit Bidirectional Voltage-Level Translator with Auto Direction Sensing and +/-15-kV ESD Protect, PW0016A (TSSOP-16); Manufacturer: Texas Instruments; SizeArea_mm2: 32.0; SizeAreaWB_mm2: 58.8; SizeX_mm: 6.4; SizeY_mm: 5.0; SizeZ_mm: 1.2; CompType: IC; U/M: EA; Green_Lifecycle: Active; Green_REACh: Passed
U8 U9 = CMP-0076549-1: TRIPLE 2-CHANNEL ANALOG MULTIPLEXER/DEMULTIPLEXER, PW0016A (TSSOP-16); Manufacturer: Texas Instruments; SizeAreaWB_mm2: 58.8; SizeArea_mm2: 32.0; SizeZ_mm: 1.2; SizeY_mm: 5.0; U/M: EA; CompType: IC; SizeX_mm: 6.4
Y2 = CMP-0080365-1: Crystal, 20 MHz, 25 ppm, 18, SMD; Manufacturer: ECS Inc.; Frequency Stability: 30 ppm; AEC Qualified: N; Frequency Tolerance: 25 ppm; AEC Category: Q200; TaMax_C: 85°C; Frequency_Fixed: 20MHz; TaMin_C: -40°C; Load Capacitance: 18

## Sheet MCU025B_F280049C_Device.SchDoc
size 431 x 279 mm; Date: Not shown in title block; ApprovedBy: Not shown in title block; CheckedBy: Not shown in title block; Author: Not shown in title block; CompanyName: Not shown in title block; Engineer: Not shown in title block; Organization: Not shown in title block; Address1: Not shown in title block; Address2: Not shown in title block; Address3: Not shown in title block; Address4: Not shown in title block; DocumentNumber: 4; Revision: Use project parameter SCH_Rev; SheetNumber: 4; SheetTotal: 8; PageSetup: Record=PageOptions¦CenterHorizontal=True¦CenterVertical=True¦PrintScale=1.00¦XCorrection=1.00¦YCorrection=1.00¦PrintKind=0¦BorderSize=5000000¦LeftOffset=0¦BottomOffset=0¦Orientation=2¦PaperLength=1000¦PaperWidth=1000¦Scale=100¦PaperSource=15¦PrintQuality=600¦MediaType=1¦DitherType=10¦PaperKind=Letter¦PrintScaleMode=1
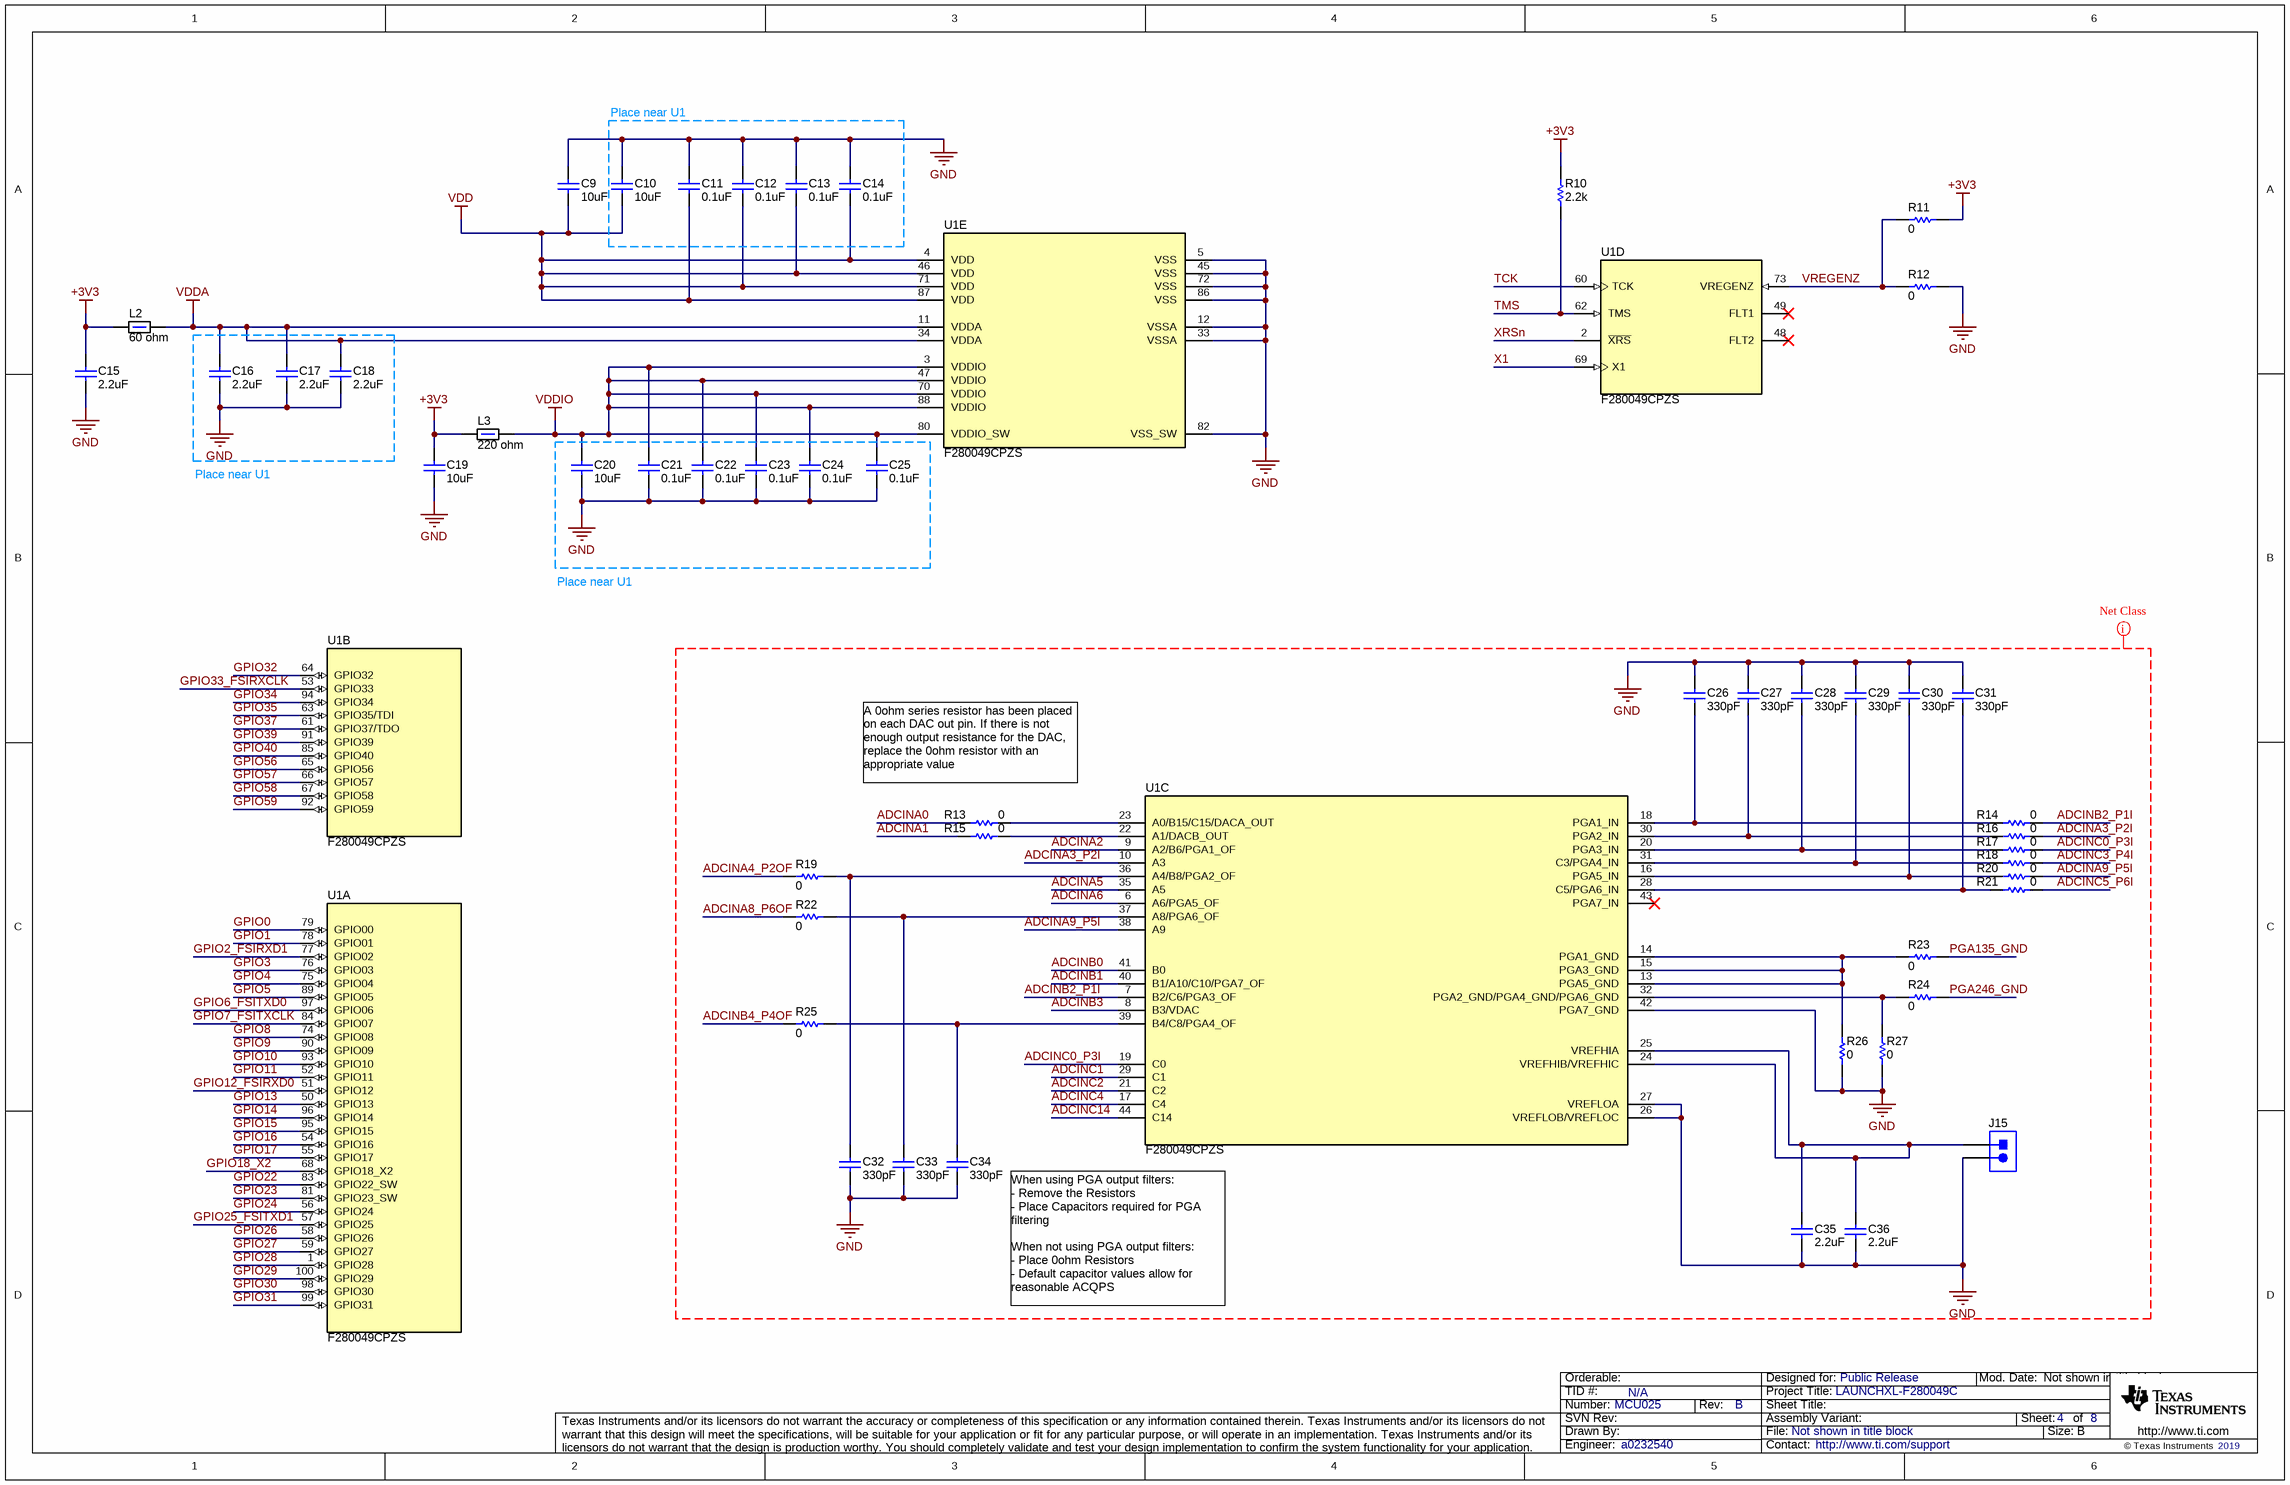
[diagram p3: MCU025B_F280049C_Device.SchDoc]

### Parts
C9  ValueDisplayed: 10uF  [0603]  (hidden comment: GRM188R61A106ME69D)
C10  ValueDisplayed: 10uF  [0603]  (hidden comment: GRM188R61A106ME69D)
C11  ValueDisplayed: 0.1uF  [0402]  (hidden comment: GRM155R71A104KA01D)
C12  ValueDisplayed: 0.1uF  [0402]  (hidden comment: GRM155R71A104KA01D)
C13  ValueDisplayed: 0.1uF  [0402]  (hidden comment: GRM155R71A104KA01D)
C14  ValueDisplayed: 0.1uF  [0402]  (hidden comment: GRM155R71A104KA01D)
C15  ValueDisplayed: 2.2uF  [0603]  (hidden comment: GRM188R61A225KE34D)
C16  ValueDisplayed: 2.2uF  [0603]  (hidden comment: GRM188R61A225KE34D)
C17  ValueDisplayed: 2.2uF  [0603]  (hidden comment: GRM188R61A225KE34D)
C18  ValueDisplayed: 2.2uF  [0603]  (hidden comment: GRM188R61A225KE34D)
C19  ValueDisplayed: 10uF  [0603]  (hidden comment: GRM188R61A106ME69D)
C20  ValueDisplayed: 10uF  [0603]  (hidden comment: GRM188R61A106ME69D)
C21  ValueDisplayed: 0.1uF  [0402]  (hidden comment: GRM155R71A104KA01D)
C22  ValueDisplayed: 0.1uF  [0402]  (hidden comment: GRM155R71A104KA01D)
C23  ValueDisplayed: 0.1uF  [0402]  (hidden comment: GRM155R71A104KA01D)
C24  ValueDisplayed: 0.1uF  [0402]  (hidden comment: GRM155R71A104KA01D)
C25  ValueDisplayed: 0.1uF  [0402]  (hidden comment: GRM155R71A104KA01D)
C26  ValueDisplayed: 330pF  [0603]  (hidden comment: GRM1885C1H331JA01D)
C27  ValueDisplayed: 330pF  [0603]  (hidden comment: GRM1885C1H331JA01D)
C28  ValueDisplayed: 330pF  [0603]  (hidden comment: GRM1885C1H331JA01D)
C29  ValueDisplayed: 330pF  [0603]  (hidden comment: GRM1885C1H331JA01D)
C30  ValueDisplayed: 330pF  [0603]  (hidden comment: GRM1885C1H331JA01D)
C31  ValueDisplayed: 330pF  [0603]  (hidden comment: GRM1885C1H331JA01D)
C32  ValueDisplayed: 330pF  [0603]  (hidden comment: GRM1885C1H331JA01D)
C33  ValueDisplayed: 330pF  [0603]  (hidden comment: GRM1885C1H331JA01D)
C34  ValueDisplayed: 330pF  [0603]  (hidden comment: GRM1885C1H331JA01D)
C35  ValueDisplayed: 2.2uF  [0603]  (hidden comment: GRM188R61A225KE34D)
C36  ValueDisplayed: 2.2uF  [0603]  (hidden comment: GRM188R61A225KE34D)
J15  61300211121  [WURTH_61300211121]  (value not drawn)
L2  ValueDisplayed: 60 ohm  [0805]  (hidden comment: BKP2125HS600-T)
L3  ValueDisplayed: 220 ohm  [0805]  (hidden comment: BLM21PG221SN1D)
R10  ValueDisplayed: 2.2k  [0402]  (hidden comment: CRCW04022K20JNED)
R11  ValueDisplayed: 0  [0603]  (hidden comment: CRCW06030000Z0EA)
R12  ValueDisplayed: 0  [0603]  (hidden comment: CRCW06030000Z0EA)
R13  ValueDisplayed: 0  [0603]  (hidden comment: CRCW06030000Z0EA)
R14  ValueDisplayed: 0  [0603]  (hidden comment: CRCW06030000Z0EA)
R15  ValueDisplayed: 0  [0603]  (hidden comment: CRCW06030000Z0EA)
R16  ValueDisplayed: 0  [0603]  (hidden comment: CRCW06030000Z0EA)
R17  ValueDisplayed: 0  [0603]  (hidden comment: CRCW06030000Z0EA)
R18  ValueDisplayed: 0  [0603]  (hidden comment: CRCW06030000Z0EA)
R19  ValueDisplayed: 0  [0603]  (hidden comment: CRCW06030000Z0EA)
R20  ValueDisplayed: 0  [0603]  (hidden comment: CRCW06030000Z0EA)
R21  ValueDisplayed: 0  [0603]  (hidden comment: CRCW06030000Z0EA)
R22  ValueDisplayed: 0  [0603]  (hidden comment: CRCW06030000Z0EA)
R23  ValueDisplayed: 0  [0603]  (hidden comment: CRCW06030000Z0EA)
R24  ValueDisplayed: 0  [0603]  (hidden comment: CRCW06030000Z0EA)
R25  ValueDisplayed: 0  [0603]  (hidden comment: CRCW06030000Z0EA)
R26  ValueDisplayed: 0  [0603]  (hidden comment: CRCW06030000Z0EA)
R27  ValueDisplayed: 0  [0603]  (hidden comment: CRCW06030000Z0EA)
U1  F280049CPZS  [PZ0100A_N]  (parts A,B,C,D,E of 5)

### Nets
+3V3: C15.1 C19.1 L2.1 L3.1 R10.2 R11.2
GND: C9.1 C10.1 C11.2 C12.2 C13.2 C14.2 C15.2 C16.2 C17.2 C18.2 C19.2 C20.2 C21.1 C22.1 C23.1 C24.1 C25.1 C26.1 C27.1 C28.1 C29.1 C30.1 C31.1 C32.2 C33.2 C34.2 C35.2 C36.2 J15.2 R12.2 R26.1 R27.1 U1.5(VSS) U1.12(VSSA) U1.26(VREFLOB/VREFLOC) U1.27(VREFLOA) U1.33(VSSA) U1.42(PGA7_GND) U1.45(VSS) U1.72(VSS) U1.82(VSS_SW) U1.86(VSS)
VDD: C9.2 C10.2 C11.1 C12.1 C13.1 C14.1 U1.4(VDD) U1.46(VDD) U1.71(VDD) U1.87(VDD)
VDDA: C16.1 C17.1 C18.1 L2.2 U1.11(VDDA) U1.34(VDDA)
VDDIO: C20.1 C21.2 C22.2 C23.2 C24.2 C25.2 L3.2 U1.3(VDDIO) U1.47(VDDIO) U1.70(VDDIO) U1.80(VDDIO_SW) U1.88(VDDIO)
ADCINA0: R13.1
ADCINA1: R15.1
ADCINA2: U1.9(A2/B6/PGA1_OF)
ADCINA3_P2I: R16.2 U1.10(A3)
ADCINA4_P2OF: R19.1
ADCINA5: U1.35(A5)
ADCINA6: U1.6(A6/PGA5_OF)
ADCINA8_P6OF: R22.1
ADCINA9_P5I: R20.2 U1.38(A9)
ADCINB0: U1.41(B0)
ADCINB1: U1.40(B1/A10/C10/PGA7_OF)
ADCINB2_P1I: R14.2 U1.7(B2/C6/PGA3_OF)
ADCINB3: U1.8(B3/VDAC)
ADCINB4_P4OF: R25.1
ADCINC0_P3I: R17.2 U1.19(C0)
ADCINC1: U1.29(C1)
ADCINC2: U1.21(C2)
ADCINC3_P4I: R18.2
ADCINC4: U1.17(C4)
ADCINC5_P6I: R21.2
ADCINC14: U1.44(C14)
GPIO0: U1.79(GPIO00)
GPIO1: U1.78(GPIO01)
GPIO2_FSIRXD1: U1.77(GPIO02)
GPIO3: U1.76(GPIO03)
GPIO4: U1.75(GPIO04)
GPIO5: U1.89(GPIO05)
GPIO6_FSITXD0: U1.97(GPIO06)
GPIO7_FSITXCLK: U1.84(GPIO07)
GPIO8: U1.74(GPIO08)
GPIO9: U1.90(GPIO09)
GPIO10: U1.93(GPIO10)
GPIO11: U1.52(GPIO11)
GPIO12_FSIRXD0: U1.51(GPIO12)
GPIO13: U1.50(GPIO13)
GPIO14: U1.96(GPIO14)
GPIO15: U1.95(GPIO15)
GPIO16: U1.54(GPIO16)
GPIO17: U1.55(GPIO17)
GPIO18_X2: U1.68(GPIO18_X2)
GPIO22: U1.83(GPIO22_SW)
GPIO23: U1.81(GPIO23_SW)
GPIO24: U1.56(GPIO24)
GPIO25_FSITXD1: U1.57(GPIO25)
GPIO26: U1.58(GPIO26)
GPIO27: U1.59(GPIO27)
GPIO28: U1.1(GPIO28)
GPIO29: U1.100(GPIO29)
GPIO30: U1.98(GPIO30)
GPIO31: U1.99(GPIO31)
GPIO32: U1.64(GPIO32)
GPIO33_FSIRXCLK: U1.53(GPIO33)
GPIO34: U1.94(GPIO34)
GPIO35: U1.63(GPIO35/TDI)
GPIO37: U1.61(GPIO37/TDO)
GPIO39: U1.91(GPIO39)
GPIO40: U1.85(GPIO40)
GPIO56: U1.65(GPIO56)
GPIO57: U1.66(GPIO57)
GPIO58: U1.67(GPIO58)
GPIO59: U1.92(GPIO59)
PGA135_GND: R23.2
PGA246_GND: R24.2
TCK: U1.60(TCK)
TMS: R10.1 U1.62(TMS)
VREGENZ: R11.1 R12.1 U1.73(VREGENZ)
X1: U1.69(X1)
XRSn: U1.2(~{XRS})
NetC26_2: C26.2 R14.1 U1.18(PGA1_IN)
NetC27_2: C27.2 R16.1 U1.30(PGA2_IN)
NetC28_2: C28.2 R17.1 U1.20(PGA3_IN)
NetC29_2: C29.2 R18.1 U1.31(C3/PGA4_IN)
NetC30_2: C30.2 R20.1 U1.16(PGA5_IN)
NetC31_2: C31.2 R21.1 U1.28(C5/PGA6_IN)
NetC32_1: C32.1 R19.2 U1.36(A4/B8/PGA2_OF)
NetC33_1: C33.1 R22.2 U1.37(A8/PGA6_OF)
NetC34_1: C34.1 R25.2 U1.39(B4/C8/PGA4_OF)
NetC35_1: C35.1 C36.1 J15.1 U1.24(VREFHIB/VREFHIC) U1.25(VREFHIA)
NetR13_2: R13.2 U1.23(A0/B15/C15/DACA_OUT)
NetR15_2: R15.2 U1.22(A1/DACB_OUT)
NetR23_1: R23.1 R26.2 U1.13(PGA5_GND) U1.14(PGA1_GND) U1.15(PGA3_GND)
NetR24_1: R24.1 R27.2 U1.32(PGA2_GND/PGA4_GND/PGA6_GND)

Not connected (* = marked no-connect by the designer): U1 43(PGA7_IN)* 48(FLT2)* 49(FLT1)*

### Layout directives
net class Analog: ADCINA0, ADCINA1, ADCINA2, ADCINA3_P2I, ADCINA4_P2OF, ADCINA5, ADCINA6, ADCINA8_P6OF, ADCINA9_P5I, ADCINB0, ADCINB1, ADCINB2_P1I, ADCINB3, ADCINB4_P4OF, ADCINC0_P3I, ADCINC1, ADCINC2, ADCINC3_P4I, ADCINC4, ADCINC5_P6I, ADCINC14, GND, PGA135_GND, PGA246_GND

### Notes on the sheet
- Place near U1
- A 0ohm series resistor has been placed on each DAC out pin. If there is not enough output resistance for the DAC, replace the 0ohm resistor with an appropriate value
- When using PGA output filters:
  - Remove the Resistors
  - Place Capacitors required for PGA filtering
  When not using PGA output filters:
  - Place 0ohm Resistors
  - Default capacitor values allow for reasonable ACQPS

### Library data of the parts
C9 C10 C19 C20 = CMP-0007318-5: CAP, CERM, 10 uF, 10 V, +/- 20%, X5R, 0603; Manufacturer: MuRata; Polarized: N; Value: 10uF; U/M: EA; Cap_F: 10µF; Value1: Unknown; VDC_V: 10V; TaMin_C: -55°C; TaMax_C: 85°C; SizeArea_mm2: 1.28; SizeAreaWB_mm2: 4.68; SizeX_mm: 1.6; SizeY_mm: 0.8; SizeZ_mm: 1; AEC Category: Q200
C11-C14 C21-C25 = CMP-0006629-2: as C49 on sheet MCU025B_Connectors
C15-C18 C35 C36 = CMP-0007323-5: CAP, CERM, 2.2 uF, 10 V, +/- 10%, X5R, 0603; Manufacturer: MuRata; Polarized: N; Value: 2.2uF; U/M: EA; Cap_F: 2.2µF; Value1: Unknown; VDC_V: 10V; TaMin_C: -55°C; TaMax_C: 85°C; SizeArea_mm2: 1.28; SizeAreaWB_mm2: 4.68; SizeX_mm: 1.6; SizeY_mm: 0.8; SizeZ_mm: 1; AEC Category: Q200
C26-C34 = CMP-0007209-4: CAP, CERM, 330 pF, 50 V, +/- 5%, C0G/NP0, 0603; Manufacturer: MuRata; Polarized: N; Value: 330pF; U/M: EA; Value1: Unknown; VDC_V: 50V; TaMin_C: -55°C; TaMax_C: 125°C; SizeArea_mm2: 1.28; SizeAreaWB_mm2: 4.68; SizeX_mm: 1.6; SizeY_mm: 0.8; SizeZ_mm: 1; AEC Category: Q200
J15 = CMP-0054794-1: Header, 2.54 mm, 2x1, Gold, TH; Manufacturer: Wurth Elektronik; Green_Lifecycle: Active; Green_REACh: Passed; CNHeader: TRUE; CT: FALSE
L2 = CMP-0003306-1: Ferrite Bead, 60 ohm @ 100 MHz, 3 A, 0805; Manufacturer: Taiyo Yuden; Value: 60 ohm; Imax_A: 3A; DCR_ohm: 0.025; Value1: 0.025 ohm; SizeAreaWB_mm2: 6.75; SizeArea_mm2: 2.5; SizeX_mm: 2; SizeY_mm: 1.25; SizeZ_mm: 1.45; ZTyp@100MHz_Ohm: 60
L3 = CMP-0003363-1: Ferrite Bead, 220 ohm @ 100 MHz, 2 A, 0805; Manufacturer: MuRata; Value: 220 ohm; Imax_A: 2A; DCR_ohm: 0.045; Value1: 0.045 ohm; SizeAreaWB_mm2: 6.75; SizeArea_mm2: 2.5; SizeX_mm: 2; SizeY_mm: 1.25; SizeZ_mm: 1.45; ZTyp@100MHz_Ohm: 220
R10 = CMP-0026890-5: as R32 on sheet MCU025B_AltRouting_Misc
R11-R27 = CMP-0025697-4: as R28 on sheet MCU025B_AltRouting_Misc
U1 = CMP-0078352-1: Piccolo Microcontroller, PZ0100A (LQFP-100); Manufacturer: Texas Instruments; SizeZ_mm: 1.6; SizeX_mm: 16; AEC Category: Q200; AEC Qualified: N; SizeArea_mm2: 256; CompType: IC; SizeAreaWB_mm2: 324

## Sheet MCU025B_XDS110_Target_Interface.SchDoc
size 431 x 279 mm; Date: Not shown in title block; ApprovedBy: Not shown in title block; CheckedBy: Not shown in title block; Author: Not shown in title block; CompanyName: Not shown in title block; Engineer: Not shown in title block; Organization: Not shown in title block; Address1: Not shown in title block; Address2: Not shown in title block; Address3: Not shown in title block; Address4: Not shown in title block; DocumentNumber: 5; Revision: Use project parameter SCH_Rev; SheetNumber: 5; SheetTotal: 8; PageSetup: Record=PageOptions¦CenterHorizontal=True¦CenterVertical=True¦PrintScale=1.00¦XCorrection=1.00¦YCorrection=1.00¦PrintKind=0¦BorderSize=5000000¦LeftOffset=0¦BottomOffset=0¦Orientation=2¦PaperLength=1000¦PaperWidth=1000¦Scale=100¦PaperSource=15¦PrintQuality=600¦MediaType=1¦DitherType=10¦PaperKind=Letter¦PrintScaleMode=1
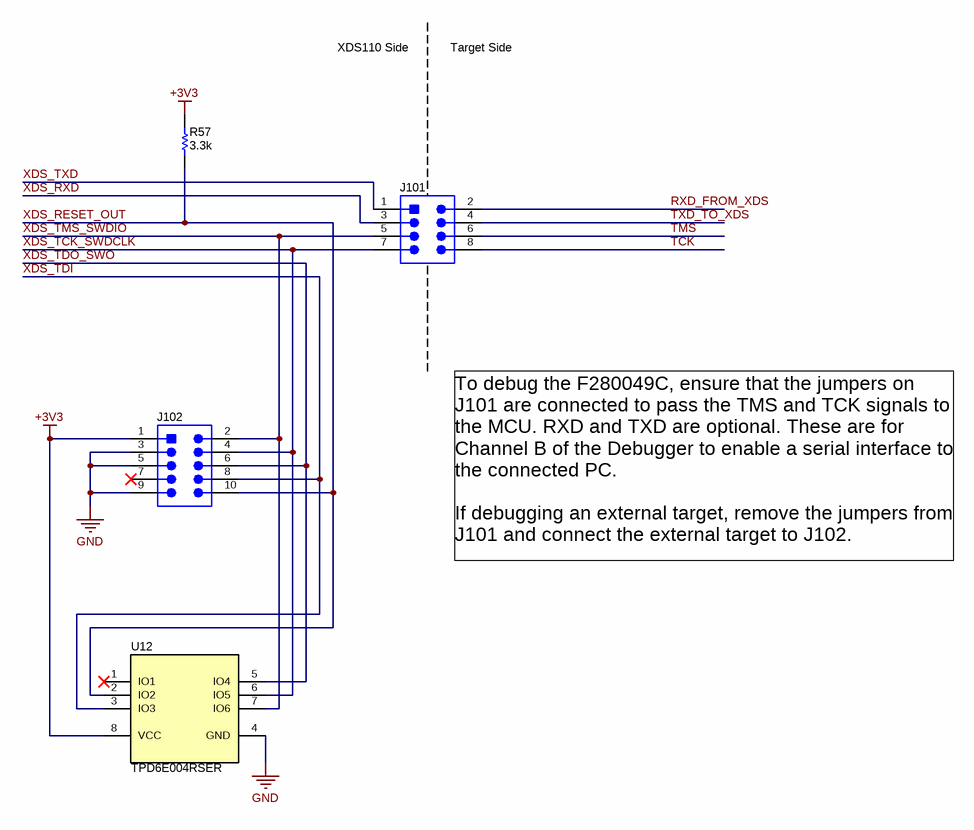
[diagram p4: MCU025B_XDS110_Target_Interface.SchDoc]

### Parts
J101  TSW-104-07-G-D  [TSW-104-07-G-D]  (value not drawn)
J102  FTSH-105-01-F-DV-K  [Samtec_FTSH-105-01-x-DV-K]  (value not drawn)
R57  ValueDisplayed: 3.3k  [0402]  (hidden comment: CRCW04023K30JNED)
U12  TPD6E004RSER  [RSE0008A]

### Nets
+3V3: J102.1 R57.2 U12.8(VCC)
GND: J102.3 J102.5 J102.9 U12.4(GND)
RXD_FROM_XDS: J101.2
TCK: J101.8
TMS: J101.6
TXD_TO_XDS: J101.4
XDS_RESET_OUT: J102.10 R57.1 U12.2(IO2)
XDS_RXD: J101.3
XDS_TCK_SWDCLK: J101.7 J102.4 U12.6(IO5)
XDS_TDI: J102.8 U12.3(IO3)
XDS_TDO_SWO: J102.6 U12.5(IO4)
XDS_TMS_SWDIO: J101.5 J102.2 U12.7(IO6)
XDS_TXD: J101.1

Not connected (* = marked no-connect by the designer): J102 7*; U12 1(IO1)*

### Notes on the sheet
- XDS110 Side
- Target Side
- To debug the F280049C, ensure that the jumpers on J101 are connected to pass the TMS and TCK signals to the MCU. RXD and TXD are optional. These are for Channel B of the Debugger to enable a serial interface to the connected PC.
  If debugging an external target, remove the jumpers from J101 and connect the external target to J102.

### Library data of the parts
J101 = CMP-0075408-1: Header, 100mil, 4x2, Gold, TH; Manufacturer: Samtec; Pitch_mm: 2.54; Cert_VDE: N; Gender: Male; Cert_CSA: Y; Voltage_V: 550V; Green_REACh: Passed; Current_A: 6.3A; CT: False; Green_Lifecycle: Active; Row_Count: 2; CNHeader: True
J102 = CMP-0075670-1: Header (Shrouded), 1.27mm, 5x2, Gold, SMT; Manufacturer: Samtec; Pitch_mm: 1.27; Gender: Male; Shrouded: Y; Row_Count: 2; Current_A: 3.3A; CNHeader: False
R57 = CMP-0026918-5: RES, 3.3 k, 5%, 0.063 W, AEC-Q200 Grade 0, 0402; Manufacturer: Vishay-Dale; Value: 3.3k; Value_Code: 3k30; Power_W: 63mW; Value2: 0.063W; VDC_V: 50V; TempCo: 200 ppm/C; SizeArea_mm2: 0.5; SizeX_mm: 1; SizeZ_mm: 0.6; EIA_Code: E24; AEC Category: Q200; AEC Qualified: Y; AEC Grade: 0
U12 = CMP-0043125-2: Low-Capacitance + / - 15 kV ESD Protection Array for High-Speed Data Interfaces, 6 Channels, -40 to +85 degC, 8-pin UQFN (RSE), Green (RoHS & no Sb/Br); Manufacturer: Texas Instruments; 1394 / Firewire: TRUE; Breakdown Voltage(Min)(V): 6; IEC 61000-4-2 Air-Gap(+/- kV): 12; IEC 61000-4-2 Contact(+/- kV): 8; IO Capacitance(Typ)(pF): 1.6; IO Leakage Current(nA): 1; SubFamily: ESD Solution

## Sheet MCU025B_XDS110_USB_Power.SchDoc
size 431 x 279 mm; Date: Not shown in title block; ApprovedBy: Not shown in title block; CheckedBy: Not shown in title block; Author: Not shown in title block; CompanyName: Not shown in title block; Engineer: Not shown in title block; Organization: Not shown in title block; Address1: Not shown in title block; Address2: Not shown in title block; Address3: Not shown in title block; Address4: Not shown in title block; DocumentNumber: 6; Revision: Use project parameter SCH_Rev; SheetNumber: 6; SheetTotal: 8; PageSetup: Record=PageOptions¦CenterHorizontal=True¦CenterVertical=True¦PrintScale=1.00¦XCorrection=1.00¦YCorrection=1.00¦PrintKind=0¦BorderSize=5000000¦LeftOffset=0¦BottomOffset=0¦Orientation=2¦PaperLength=1000¦PaperWidth=1000¦Scale=100¦PaperSource=15¦PrintQuality=600¦MediaType=1¦DitherType=10¦PaperKind=Letter¦PrintScaleMode=1
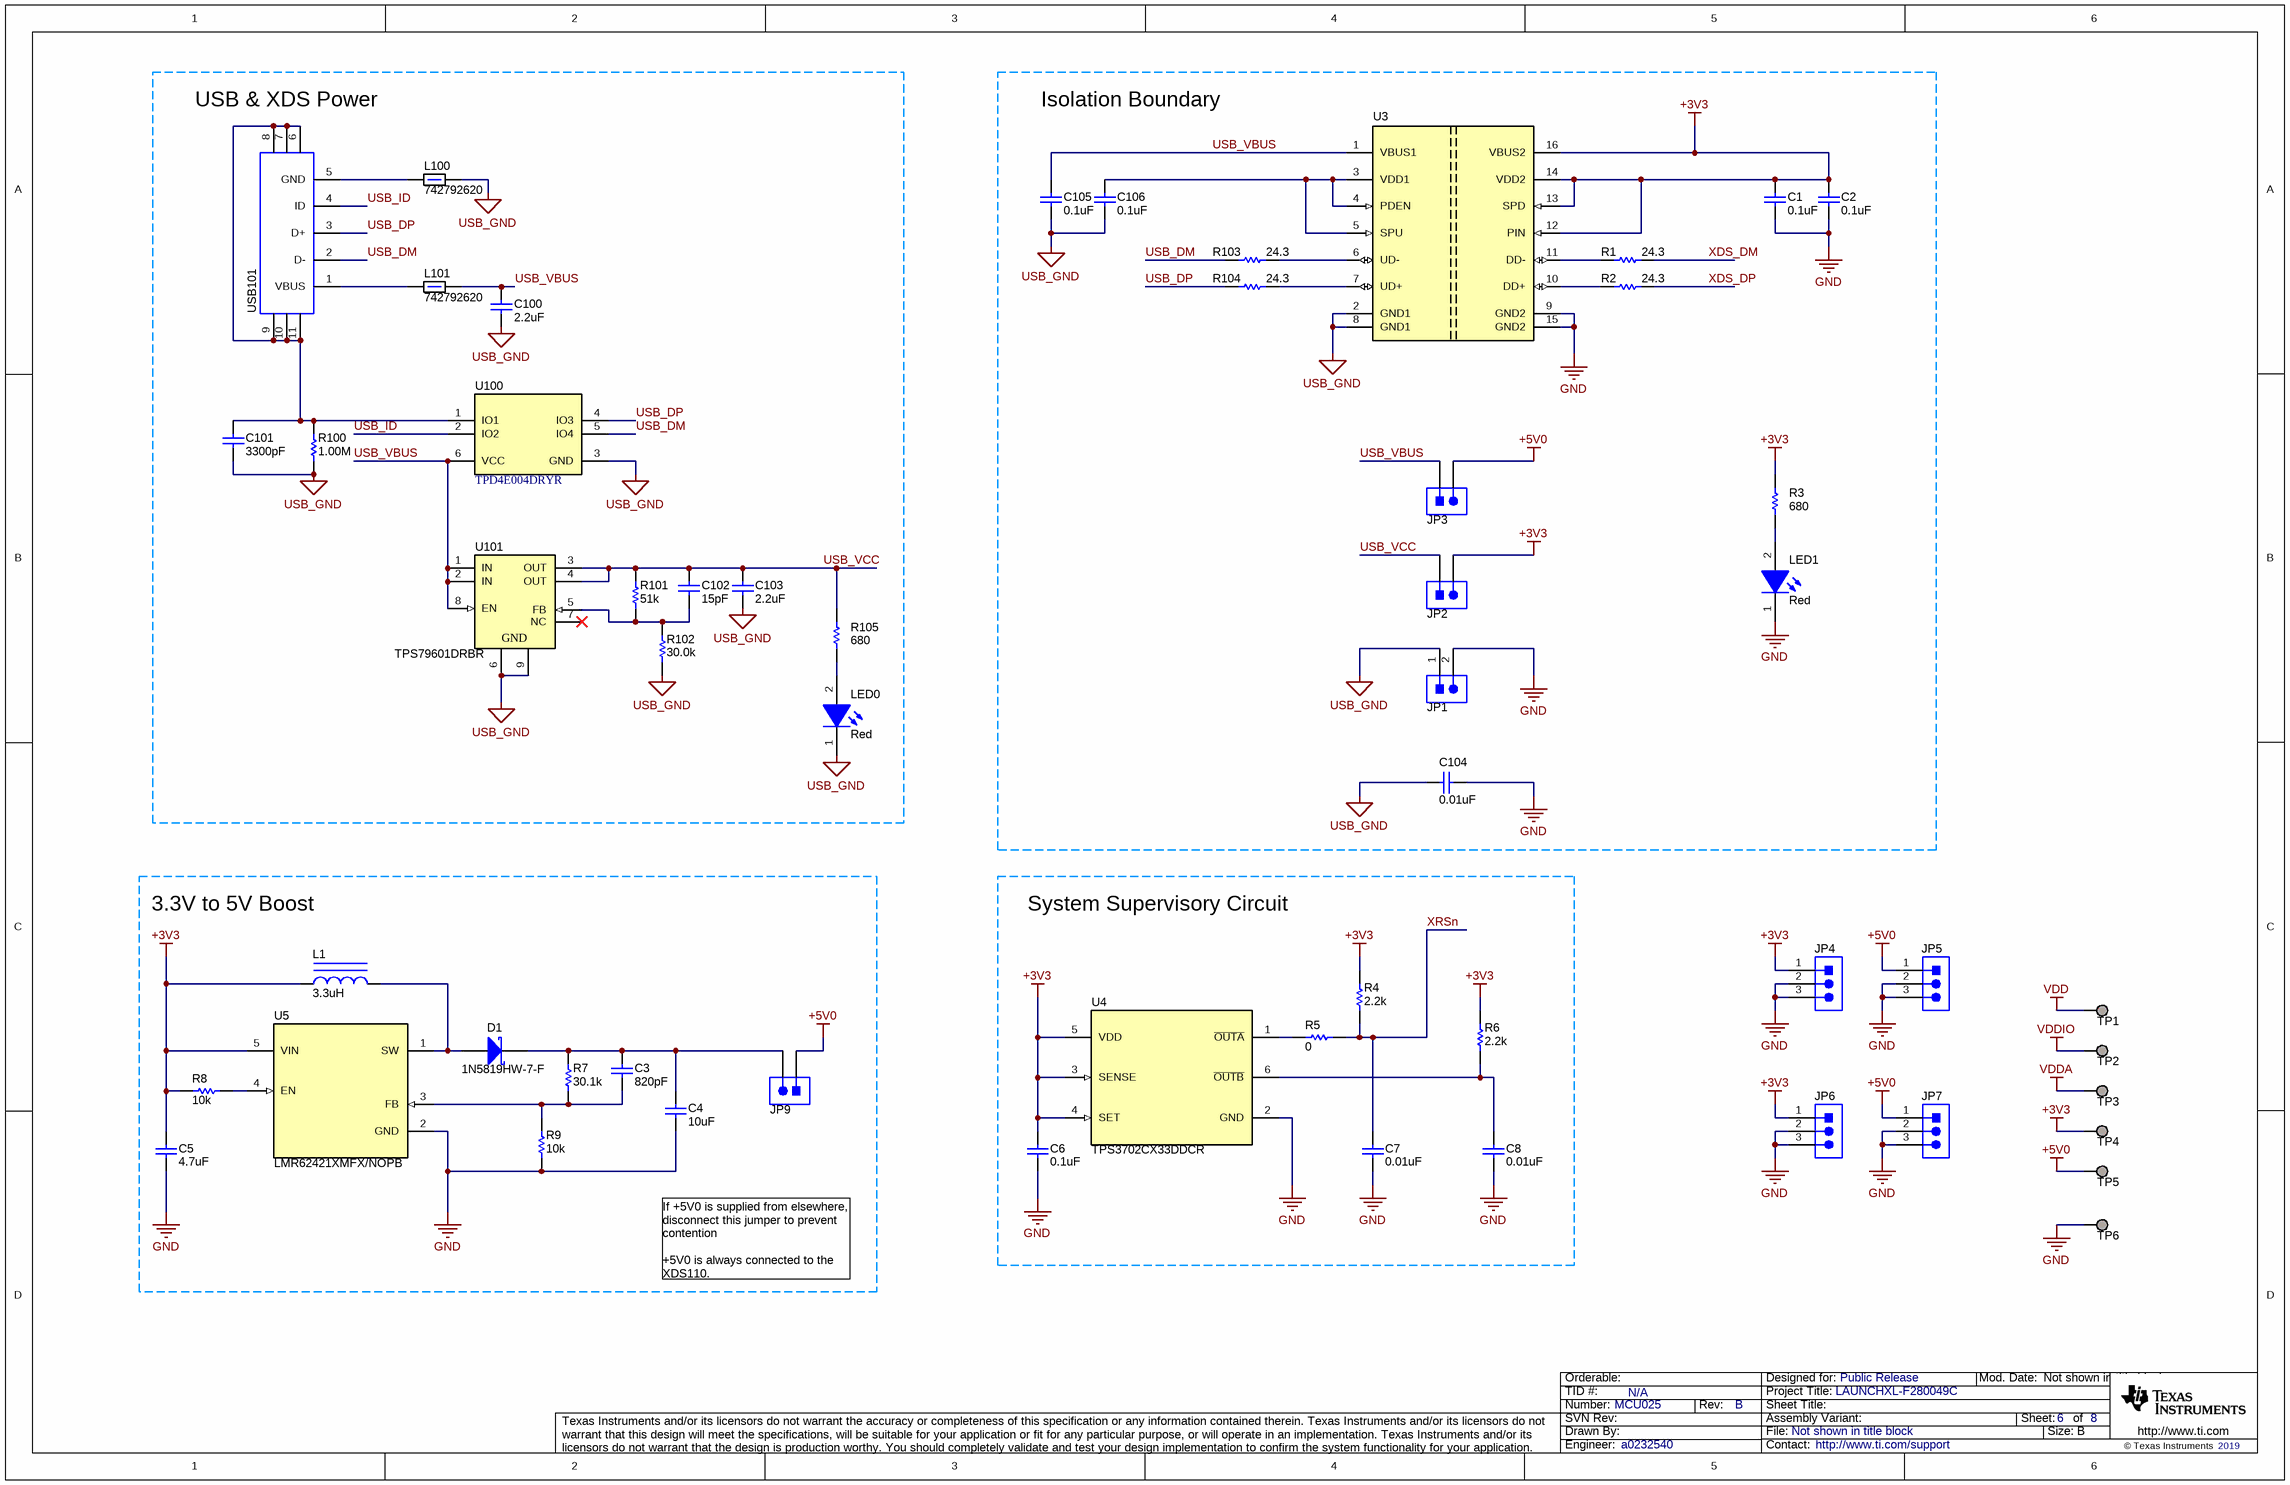
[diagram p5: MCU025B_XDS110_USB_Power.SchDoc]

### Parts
C1  ValueDisplayed: 0.1uF  [0402]  (hidden comment: GRM155R71A104KA01D)
C2  ValueDisplayed: 0.1uF  [0402]  (hidden comment: GRM155R71A104KA01D)
C3  ValueDisplayed: 820pF  [0402]  (hidden comment: GRM1555C1H821JA01D)
C4  ValueDisplayed: 10uF  [1210_220]  (hidden comment: GRM32DR71E106KA12L)
C5  ValueDisplayed: 4.7uF  [0402]  (hidden comment: GRM155R60J475ME47D)
C6  ValueDisplayed: 0.1uF  [0402]  (hidden comment: GRM155R71A104KA01D)
C7  ValueDisplayed: 0.01uF  [0402]  (hidden comment: GRM155R71E103KA01D)
C8  ValueDisplayed: 0.01uF  [0402]  (hidden comment: GRM155R71E103KA01D)
C100  ValueDisplayed: 2.2uF  [0402]  (hidden comment: GRM155R60J225KE95D)
C101  ValueDisplayed: 3300pF  [0402]  (hidden comment: GRM155R71H332KA01D)
C102  ValueDisplayed: 15pF  [0402]  (hidden comment: GRM1555C1H150JA01D)
C103  ValueDisplayed: 2.2uF  [0402]  (hidden comment: GRM155R60J225KE95D)
C104  ValueDisplayed: 0.01uF  [1812]  (hidden comment: 1812SC103KAT1A)
C105  ValueDisplayed: 0.1uF  [0402]  (hidden comment: GRM155R71A104KA01D)
C106  ValueDisplayed: 0.1uF  [0402]  (hidden comment: GRM155R71A104KA01D)
D1  1N5819HW-7-F  [SOD-123]
JP1  61300211121  [WURTH_61300211121]  (value not drawn)
JP2  61300211121  [WURTH_61300211121]  (value not drawn)
JP3  61300211121  [WURTH_61300211121]  (value not drawn)
JP4  61300311121  [WURTH_61300311121]  (value not drawn)
JP5  61300311121  [WURTH_61300311121]  (value not drawn)
JP6  61300311121  [WURTH_61300311121]  (value not drawn)
JP7  61300311121  [WURTH_61300311121]  (value not drawn)
JP9  61300211121  [WURTH_61300211121]  (value not drawn)
L1  ValueDisplayed: 3.3uH  [WE-TPC_2828]  (hidden comment: 744025003)
L100  742792620  [0603]
L101  742792620  [0603]
LED0  value Red  [WL-SMCW_RED_0805]  (hidden comment: 150080SS75000)
LED1  value Red  [WL-SMCW_RED_0805]  (hidden comment: 150080SS75000)
R1  ValueDisplayed: 24.3  [0402]  (hidden comment: CRCW040224R3FKED)
R2  ValueDisplayed: 24.3  [0402]  (hidden comment: CRCW040224R3FKED)
R3  ValueDisplayed: 680  [0402]  (hidden comment: CRCW0402680RJNED)
R4  ValueDisplayed: 2.2k  [0402]  (hidden comment: CRCW04022K20JNED)
R5  ValueDisplayed: 0  [0402]  (hidden comment: CRCW04020000Z0ED)
R6  ValueDisplayed: 2.2k  [0603]  (hidden comment: CRCW06032K20JNEA)
R7  ValueDisplayed: 30.1k  [0402]  (hidden comment: RC0402FR-0730K1L)
R8  ValueDisplayed: 10k  [0402]  (hidden comment: CRCW040210K0JNED)
R9  ValueDisplayed: 10k  [0402]  (hidden comment: CRCW040210K0JNED)
R100  ValueDisplayed: 1.00M  [0402]  (hidden comment: CRCW04021M00FKED)
R101  ValueDisplayed: 51k  [0402]  (hidden comment: CRCW040251K0FKED)
R102  ValueDisplayed: 30.0k  [0402]  (hidden comment: CRCW040230K0FKED)
R103  ValueDisplayed: 24.3  [0402]  (hidden comment: CRCW040224R3FKED)
R104  ValueDisplayed: 24.3  [0402]  (hidden comment: CRCW040224R3FKED)
R105  ValueDisplayed: 680  [0402]  (hidden comment: CRCW0402680RJNED)
TP1  TESTPOINT  [TESTPOINT]  (value not drawn)  (no BOM)
TP2  TESTPOINT  [TESTPOINT]  (value not drawn)  (no BOM)
TP3  TESTPOINT  [TESTPOINT]  (value not drawn)  (no BOM)
TP4  TESTPOINT  [TESTPOINT]  (value not drawn)  (no BOM)
TP5  TESTPOINT  [TESTPOINT]  (value not drawn)  (no BOM)
TP6  TESTPOINT  [TESTPOINT]  (value not drawn)  (no BOM)
U3  ADuM3160BRWZ  [SOIC-16]  (value not drawn)
U4  TPS3702CX33DDCR  [DDC0006A_N]
U5  LMR62421XMFX/NOPB  [DBV0005A_N]
U100  TPD4E004DRYR  [DRY0006A]
U101  TPS79601DRBR  [DRB0008B]
USB101  1051640001  [Molex_1051640001]  (value not drawn)

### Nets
+3V3: C1.2 C2.2 C5.1 C6.2 JP2.2 JP4.1 JP6.1 L1.1 R3.2 R4.2 R6.2 R8.2 TP4.1 U3.12(PIN) U3.13(SPD) U3.14(VDD2) U3.16(VBUS2) U4.3(SENSE) U4.4(SET) U4.5(VDD) U5.5(VIN)
+5V0: JP3.2 JP5.1 JP7.1 JP9.1 TP5.1
GND: C1.1 C2.1 C4.2 C5.2 C6.1 C7.2 C8.2 C104.1 JP1.2 JP4.2 JP4.3 JP5.2 JP5.3 JP6.2 JP6.3 JP7.2 JP7.3 LED1.1(K) R9.1 TP6.1 U3.9(GND2) U3.15(GND2) U4.2(GND) U5.2(GND)
USB_GND: C100.2 C101.2 C103.2 C104.2 C105.1 C106.1 JP1.1 L100.2 LED0.1(K) R100.1 R102.1 U3.2(GND1) U3.8(GND1) U100.3(GND) U101.6(GND) U101.9(GND)
VDD: TP1.1
VDDA: TP3.1
VDDIO: TP2.1
USB_DM: R103.1 U100.5(IO4) USB101.2(D-)
USB_DP: R104.1 U100.4(IO3) USB101.3(D+)
USB_ID: U100.2(IO2) USB101.4(ID)
USB_VBUS: C100.1 C105.2 JP3.1 L101.2 U3.1(VBUS1) U100.6(VCC) U101.1(IN) U101.2(IN) U101.8(EN)
USB_VCC: C102.1 C103.1 JP2.1 R101.2 R105.2 U101.3(OUT) U101.4(OUT)
XDS_DM: R1.2
XDS_DP: R2.2
XRSn: C7.1 R4.1 R5.2
NetC3_1: C3.1 C4.1 D1.1(K) JP9.2 R7.2
NetC3_2: C3.2 R7.1 R9.2 U5.3(FB)
NetC8_1: C8.1 R6.1 U4.6(~{OUTB})
NetC101_1: C101.1 R100.2 U100.1(IO1) USB101.6 USB101.7 USB101.8 USB101.9 USB101.10 USB101.11
NetC102_2: C102.2 R101.1 R102.2 U101.5(FB)
NetC106_2: C106.2 U3.3(VDD1) U3.4(PDEN) U3.5(SPU)
NetD1_2: D1.2(A) L1.2 U5.1(SW)
NetL100_1: L100.1 USB101.5(GND)
NetL101_1: L101.1 USB101.1(VBUS)
NetLED0_2: LED0.2(A) R105.1
NetLED1_2: LED1.2(A) R3.1
NetR1_1: R1.1 U3.11(DD-)
NetR2_1: R2.1 U3.10(DD+)
NetR5_1: R5.1 U4.1(~{OUTA})
NetR8_1: R8.1 U5.4(EN)
NetR103_2: R103.2 U3.6(UD-)
NetR104_2: R104.2 U3.7(UD+)

Not connected (* = marked no-connect by the designer): U101 7(NC)*

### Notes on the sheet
- (near USB101) USB & XDS Power
- Isolation Boundary
- 3.3V to 5V Boost
- System Supervisory Circuit
- If +5V0 is supplied from elsewhere, disconnect this jumper to prevent contention
  +5V0 is always connected to the XDS110.

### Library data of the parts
C1 C2 C6 C105 C106 = CMP-0006629-2: as C49 on sheet MCU025B_Connectors
C3 = CMP-0006493-2: CAP, CERM, 820 pF, 50 V, +/- 5%, C0G/NP0, 0402; Manufacturer: MuRata; Polarized: N; Value: 820pF; U/M: EA; Value1: Unknown; VDC_V: 50V; TaMin_C: -55°C; TaMax_C: 125°C; SizeArea_mm2: 0.5; SizeAreaWB_mm2: 3; SizeX_mm: 1; SizeZ_mm: 0.6; AEC Category: Q200
C4 = CMP-0009190-2: CAP, CERM, 10 uF, 25 V, +/- 10%, X7R, 1210; Manufacturer: MuRata; Polarized: N; Value: 10uF; U/M: EA; Cap_F: 10µF; Value1: Unknown; VDC_V: 25V; TaMin_C: -55°C; TaMax_C: 125°C; Cap_Case: 1210; SizeArea_mm2: 8; SizeAreaWB_mm2: 14.7; SizeX_mm: 3.2; SizeY_mm: 2.5; SizeZ_mm: 2.2; AEC Category: Q200
C5 = CMP-0006552-2: CAP, CERM, 4.7 uF, 6.3 V, +/- 20%, X5R, 0402; Manufacturer: MuRata; Polarized: N; Value: 4.7uF; U/M: EA; Cap_F: 4.7µF; Value1: Unknown; VDC_V: 6.3V; TaMin_C: -55°C; TaMax_C: 85°C; SizeArea_mm2: 0.5; SizeAreaWB_mm2: 3; SizeX_mm: 1; SizeZ_mm: 0.6; AEC Category: Q200
C7 C8 = CMP-0006658-2: CAP, CERM, 0.01 uF, 25 V, +/- 10%, X7R, 0402; Manufacturer: MuRata; Polarized: N; Value: 0.01uF; U/M: EA; Cap_F: 10nF; Value1: Unknown; VDC_V: 25V; TaMin_C: -55°C; TaMax_C: 125°C; SizeArea_mm2: 0.5; SizeAreaWB_mm2: 3; SizeX_mm: 1; SizeZ_mm: 0.6; AEC Category: Q200
C100 C103 = CMP-0006543-2: CAP, CERM, 2.2 uF, 6.3 V, +/- 10%, X5R, 0402; Manufacturer: MuRata; Polarized: N; Value: 2.2uF; U/M: EA; Cap_F: 2.2µF; Value1: Unknown; VDC_V: 6.3V; TaMin_C: -55°C; TaMax_C: 85°C; SizeArea_mm2: 0.5; SizeAreaWB_mm2: 3; SizeX_mm: 1; SizeZ_mm: 0.6; AEC Category: Q200
C101 = CMP-0006688-2: CAP, CERM, 3300 pF, 50 V, +/- 10%, X7R, 0402; Manufacturer: MuRata; Polarized: N; Value: 3300pF; U/M: EA; Cap_F: 3.3nF; Value1: Unknown; VDC_V: 50V; TaMin_C: -55°C; TaMax_C: 125°C; SizeArea_mm2: 0.5; SizeAreaWB_mm2: 3; SizeX_mm: 1; SizeZ_mm: 0.6; AEC Category: Q200
C102 = CMP-0006420-2: as C38 on sheet MCU025B_AltRouting_Misc
C104 = CMP-0009297-2: CAP, CERM, 0.01 uF, 1500 V, +/- 10%, X7R, 1812; Manufacturer: AVX; Polarized: N; Value: 0.01uF; U/M: EA; Cap_F: 10nF; ESR_ohm: 0.05; Value1: 0.05 ohm; VDC_V: 1.5kV; Value2: 1500V; TaMin_C: -55°C; TaMax_C: 125°C; SizeArea_mm2: 14.4; SizeAreaWB_mm2: 23.1; SizeX_mm: 4.5; SizeY_mm: 3.2; SizeZ_mm: 1.35; AEC Category: Q200
D1 = CMP-0028360-1: Diode, Schottky, 40 V, 1 A, SOD-123; Manufacturer: Diodes Inc.; U/M: EA; Vf_V: 4.5dV; Value: 40V; Value1: 1A; Value2: 0.45V; TJmax_C: 125°C; SizeAreaWB_mm2: 13.095; SizeArea_mm2: 6.545; SizeX_mm: 3.85; SizeY_mm: 1.7; SizeZ_mm: 1.35; AEC Category: Q101; Green_Lifecycle: Active; Green_REACh: Passed
JP1-JP3 JP9 = CMP-0054794-1: as J15 on sheet MCU025B_F280049C_Device
JP4-JP7 = CMP-0054796-1: as J14 on sheet MCU025B_Connectors
L1 = CMP-0063754-1: Inductor, Shielded Drum Core, Ferrite, 3.3 uH, 1.5 A, 0.085 ohm, SMD; Manufacturer: Wurth Elektronik; Value: 3.3uH; Ind_H: 3.3µH; Imax_A: 1.5A; Irms: 1.5A @ 40C rise; Isat: 1.8A @ 35% inductance drop; DCR_ohm: 0.085; SizeAreaWB_mm2: 14.44; SizeArea_mm2: 7.84; SizeX_mm: 2.8; SizeZ_mm: 3; AEC Category: Q200; Green_Lifecycle: Active; Green_REACh: Passed
L100 L101 = CMP-0003183-2: Ferrite Bead, 100 ohm @ 100 MHz, 0.5 A, 0603; Manufacturer: Wurth Elektronik; Ztyp@1GHz_Ohm: 137.267; ZTyp@100MHz_Ohm: 100; SizeAreaWB_mm2: 4.68; DCR_ohm: 1.5d; Value1: 0.15 ohm; Value: 100 ohm; Imax_A: 5dA; SizeZ_mm: 1; SizeX_mm: 1.6; SizeY_mm: 0.8; Value2: 0.5A; SizeArea_mm2: 1.28
LED0 LED1 = CMP-0002951-2: as LED4 on sheet MCU025B_AltRouting_Misc
R1 R2 R103 R104 = CMP-0026197-2: RES, 24.3, 1%, 0.063 W, AEC-Q200 Grade 0, 0402; Manufacturer: Vishay-Dale; Value: 24.3; Value_Code: 24R3; Power_W: 63mW; Value2: 0.063W; VDC_V: 50V; TempCo: 100 ppm/C; SizeArea_mm2: 0.5; SizeX_mm: 1; SizeZ_mm: 0.6; EIA_Code: E96; AEC Category: Q200; AEC Qualified: Y; AEC Grade: 0
R3 R105 = CMP-0026962-3: as R29 on sheet MCU025B_AltRouting_Misc
R4 = CMP-0026890-5: as R32 on sheet MCU025B_AltRouting_Misc
R5 = CMP-0026822-3: RES, 0, 5%, 0.063 W, AEC-Q200 Grade 0, 0402; Manufacturer: Vishay-Dale; Value: 0; Value_Code: 0000; Power_W: 63mW; Value2: 0.063W; VDC_V: 50V; TempCo: 200 ppm/C; SizeArea_mm2: 0.5; SizeX_mm: 1; SizeZ_mm: 0.6; EIA_Code: E24; AEC Category: Q200; AEC Qualified: Y
R6 = CMP-0025769-4: as R42 on sheet MCU025B_AltRouting_Misc
R7 = CMP-0026730-1: RES, 30.1 k, 1%, 0.063 W, 0402; Manufacturer: Yageo America; Value: 30.1k; Value_Code: 30k1; Power_W: 63mW; Value2: 0.063W; VDC_V: 50V; TempCo: 100 ppm/C; SizeArea_mm2: 0.5; SizeX_mm: 1; SizeZ_mm: 0.6; EIA_Code: E96; U/M: EA; AEC Category: Q200; AEC Qualified: N
R8 R9 = CMP-0026825-5: RES, 10 k, 5%, 0.063 W, AEC-Q200 Grade 0, 0402; Manufacturer: Vishay-Dale; Value: 10k; Value_Code: 10k0; Power_W: 63mW; Value2: 0.063W; VDC_V: 50V; TempCo: 200 ppm/C; SizeArea_mm2: 0.5; SizeX_mm: 1; SizeZ_mm: 0.6; EIA_Code: E24; AEC Category: Q200; AEC Qualified: Y; AEC Grade: 0
R100 = CMP-0026100-2: RES, 1.00 M, 1%, 0.063 W, AEC-Q200 Grade 0, 0402; Manufacturer: Vishay-Dale; Value: 1.00Meg; Res_ohm: 1M; Value_Code: 1M00; Power_W: 63mW; Value2: 0.063W; VDC_V: 50V; TempCo: 100 ppm/C; SizeArea_mm2: 0.5; SizeX_mm: 1; SizeZ_mm: 0.6; EIA_Code: E96; AEC Category: Q200; AEC Qualified: Y; AEC Grade: 0
R101 = CMP-0088102-2: RES Thick Film SMD 51kΩ 1% 1/16W 0402 100ppm/K; Manufacturer: Vishay; SizeX_mm: 1; Power_W: 63mW; AEC Qualified: Yes; VDC_V: 50V; SizeZ_mm: 0.6; SizeY_mm: 0.5; AEC Grade: Grade 0
R102 = CMP-0078244-2: RES, 30.0 k, 1%, 0.063 W, AEC-Q200 Grade 0, 0402; Manufacturer: Vishay-Dale; Power_W: 63mW; Green_Lifecycle: Active; TempCo: 100 ppm/C; Value_Code: 30k0; Green_REACh: Passed; Value: 30.0k; Res_ohm: 30k; SizeX_mm: 1; SizeY_mm: 0.5; SizeZ_mm: 0.6; Value2: 0.063W; AEC Qualified: Y; VDC_V: 50V; AEC Grade: 0; AEC Category: Q200
TP1-TP6 = CMP-0078143-2: TEST POINT.  No entry in BOM.
U3 = CMP-0074604-2: Full/Low Speed 2.5 kV USB Digital Isolator, SOIC-16; Manufacturer: Analog Devices
U4 = CMP-0067340-2: High-Accuracy, Fixed-Threshold OV/UV Monitor, DDC0006A (SOT-23-T-6); Alternate PartNumber: TPS3702CX33DDCT; Manufacturer: Texas Instruments; SizeArea_mm2: 4.8675; SizeAreaWB_mm2: 10.4675; SizeX_mm: 1.65; SizeY_mm: 2.95; SizeZ_mm: 0.87; CompType: IC; U/M: EA
U5 = CMP-0066119-1: SIMPLE SWITCHER 2.7V to 5.5V, 2.1A Step-Up Regulator in SOT-23, DBV0005A (SOT-23-5); Alternate PartNumber: LMR62421XMFE/NOPB; Manufacturer: Texas Instruments; SizeArea_mm2: 8.12; SizeAreaWB_mm2: 14.82; SizeX_mm: 2.8; SizeY_mm: 2.9; SizeZ_mm: 1.45; CompType: IC; U/M: EA; Green_Lifecycle: Active; Green_REACh: Passed
U100 = CMP-0043115-2: ESD-Protection Array for High-Speed Data Interfaces, 4 Channels, -40 to +85 degC, 6-pin SON (DRY), Green (RoHS & no Sb/Br); Manufacturer: Texas Instruments; 1394 / Firewire: TRUE; Breakdown Voltage(Min)(V): 6; IEC 61000-4-2 Air-Gap(+/- kV): 12; IEC 61000-4-2 Contact(+/- kV): 8; IO Capacitance(Typ)(pF): 1.6; IO Leakage Current(nA): 1; SubFamily: ESD Solution; AEC Category: Q200; AEC Qualified: N; CompType: IC; SizeArea_mm2: 1.45; SizeAreaWB_mm2: 4.9; SizeX_mm: 1.0; SizeZ_mm: 0.6
U101 = CMP-0036402-3: Single Output High PSRR LDO, 1 A, Adjustable 1.2 to 5.5 V Output, 2.7 to 5.5 V Input, 8-pin SON (DRB), -40 to 125 degC, Green (RoHS & no Sb/Br); Manufacturer: Texas Instruments; Accuracy(%): 2; Iout(Max)(A): 1; Iq(Typ)(mA): 0.26; SubFamily: Single Channel LDO; Vdo(Typ)(mV): 250; Vin(Max)(V): 5.5; Vin(Min)(V): 2.7; Vout Adj(Min)(V): 1.2; AEC Category: Q200; AEC Qualified: N; CompType: IC; SizeAreaWB_mm2: 16.0; SizeArea_mm2: 9.0; SizeX_mm: 3.0; SizeZ_mm: 1.0
USB101 = CMP-0055311-1: Receptacle, USB 2.0, Micro B, 5 Position, R/A, SMT; Manufacturer: Molex; Pitch_mm: 0.65; Gender: Female; ContactFinish: Gold; Current_A: 1.8A; Voltage_V: 30V; Cert_UL: Y; CNHeader: FALSE; CT: TRUE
